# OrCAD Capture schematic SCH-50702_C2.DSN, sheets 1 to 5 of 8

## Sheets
1 01. TITLE PAGE: title: KW45B41Z-LOC; rev: C2; company: NXP Semiconductors; note: SCH-50702 PDF: SPF-50702; note: 6501 William Cannon Drive West; note: Austin, TX 78735-8598
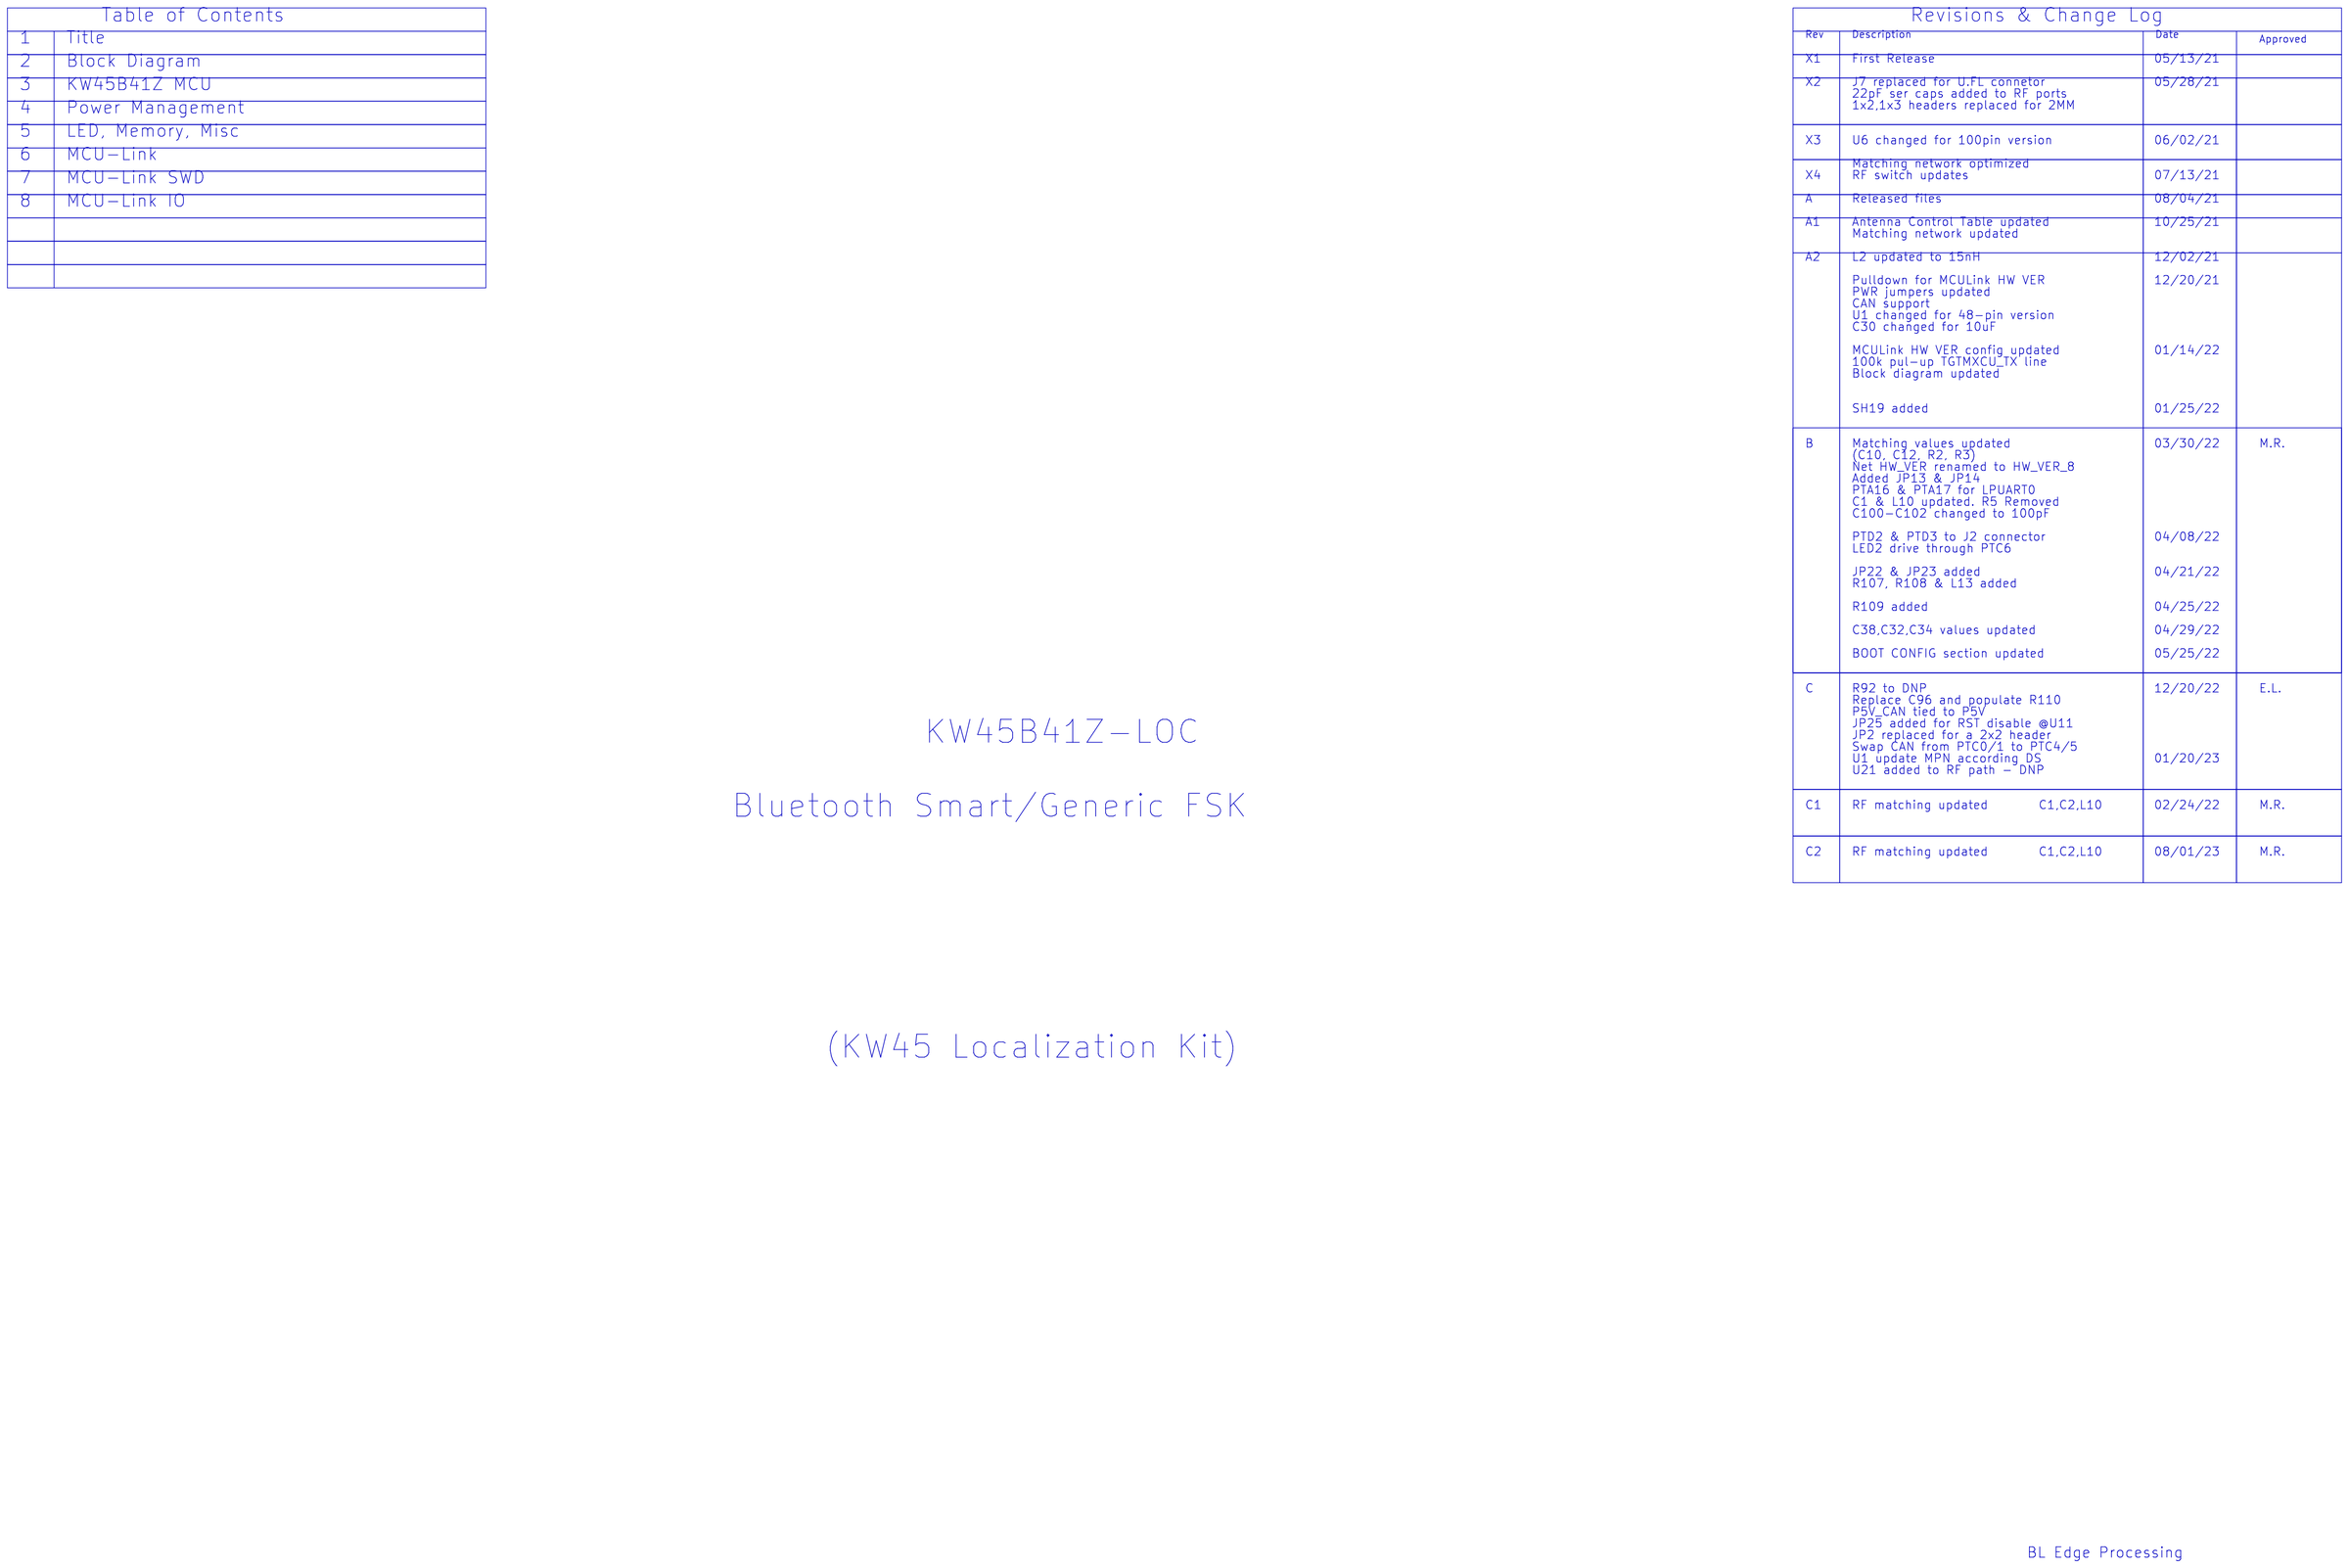
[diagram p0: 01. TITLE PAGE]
2 02. BLOCK DIAGRAM: size C
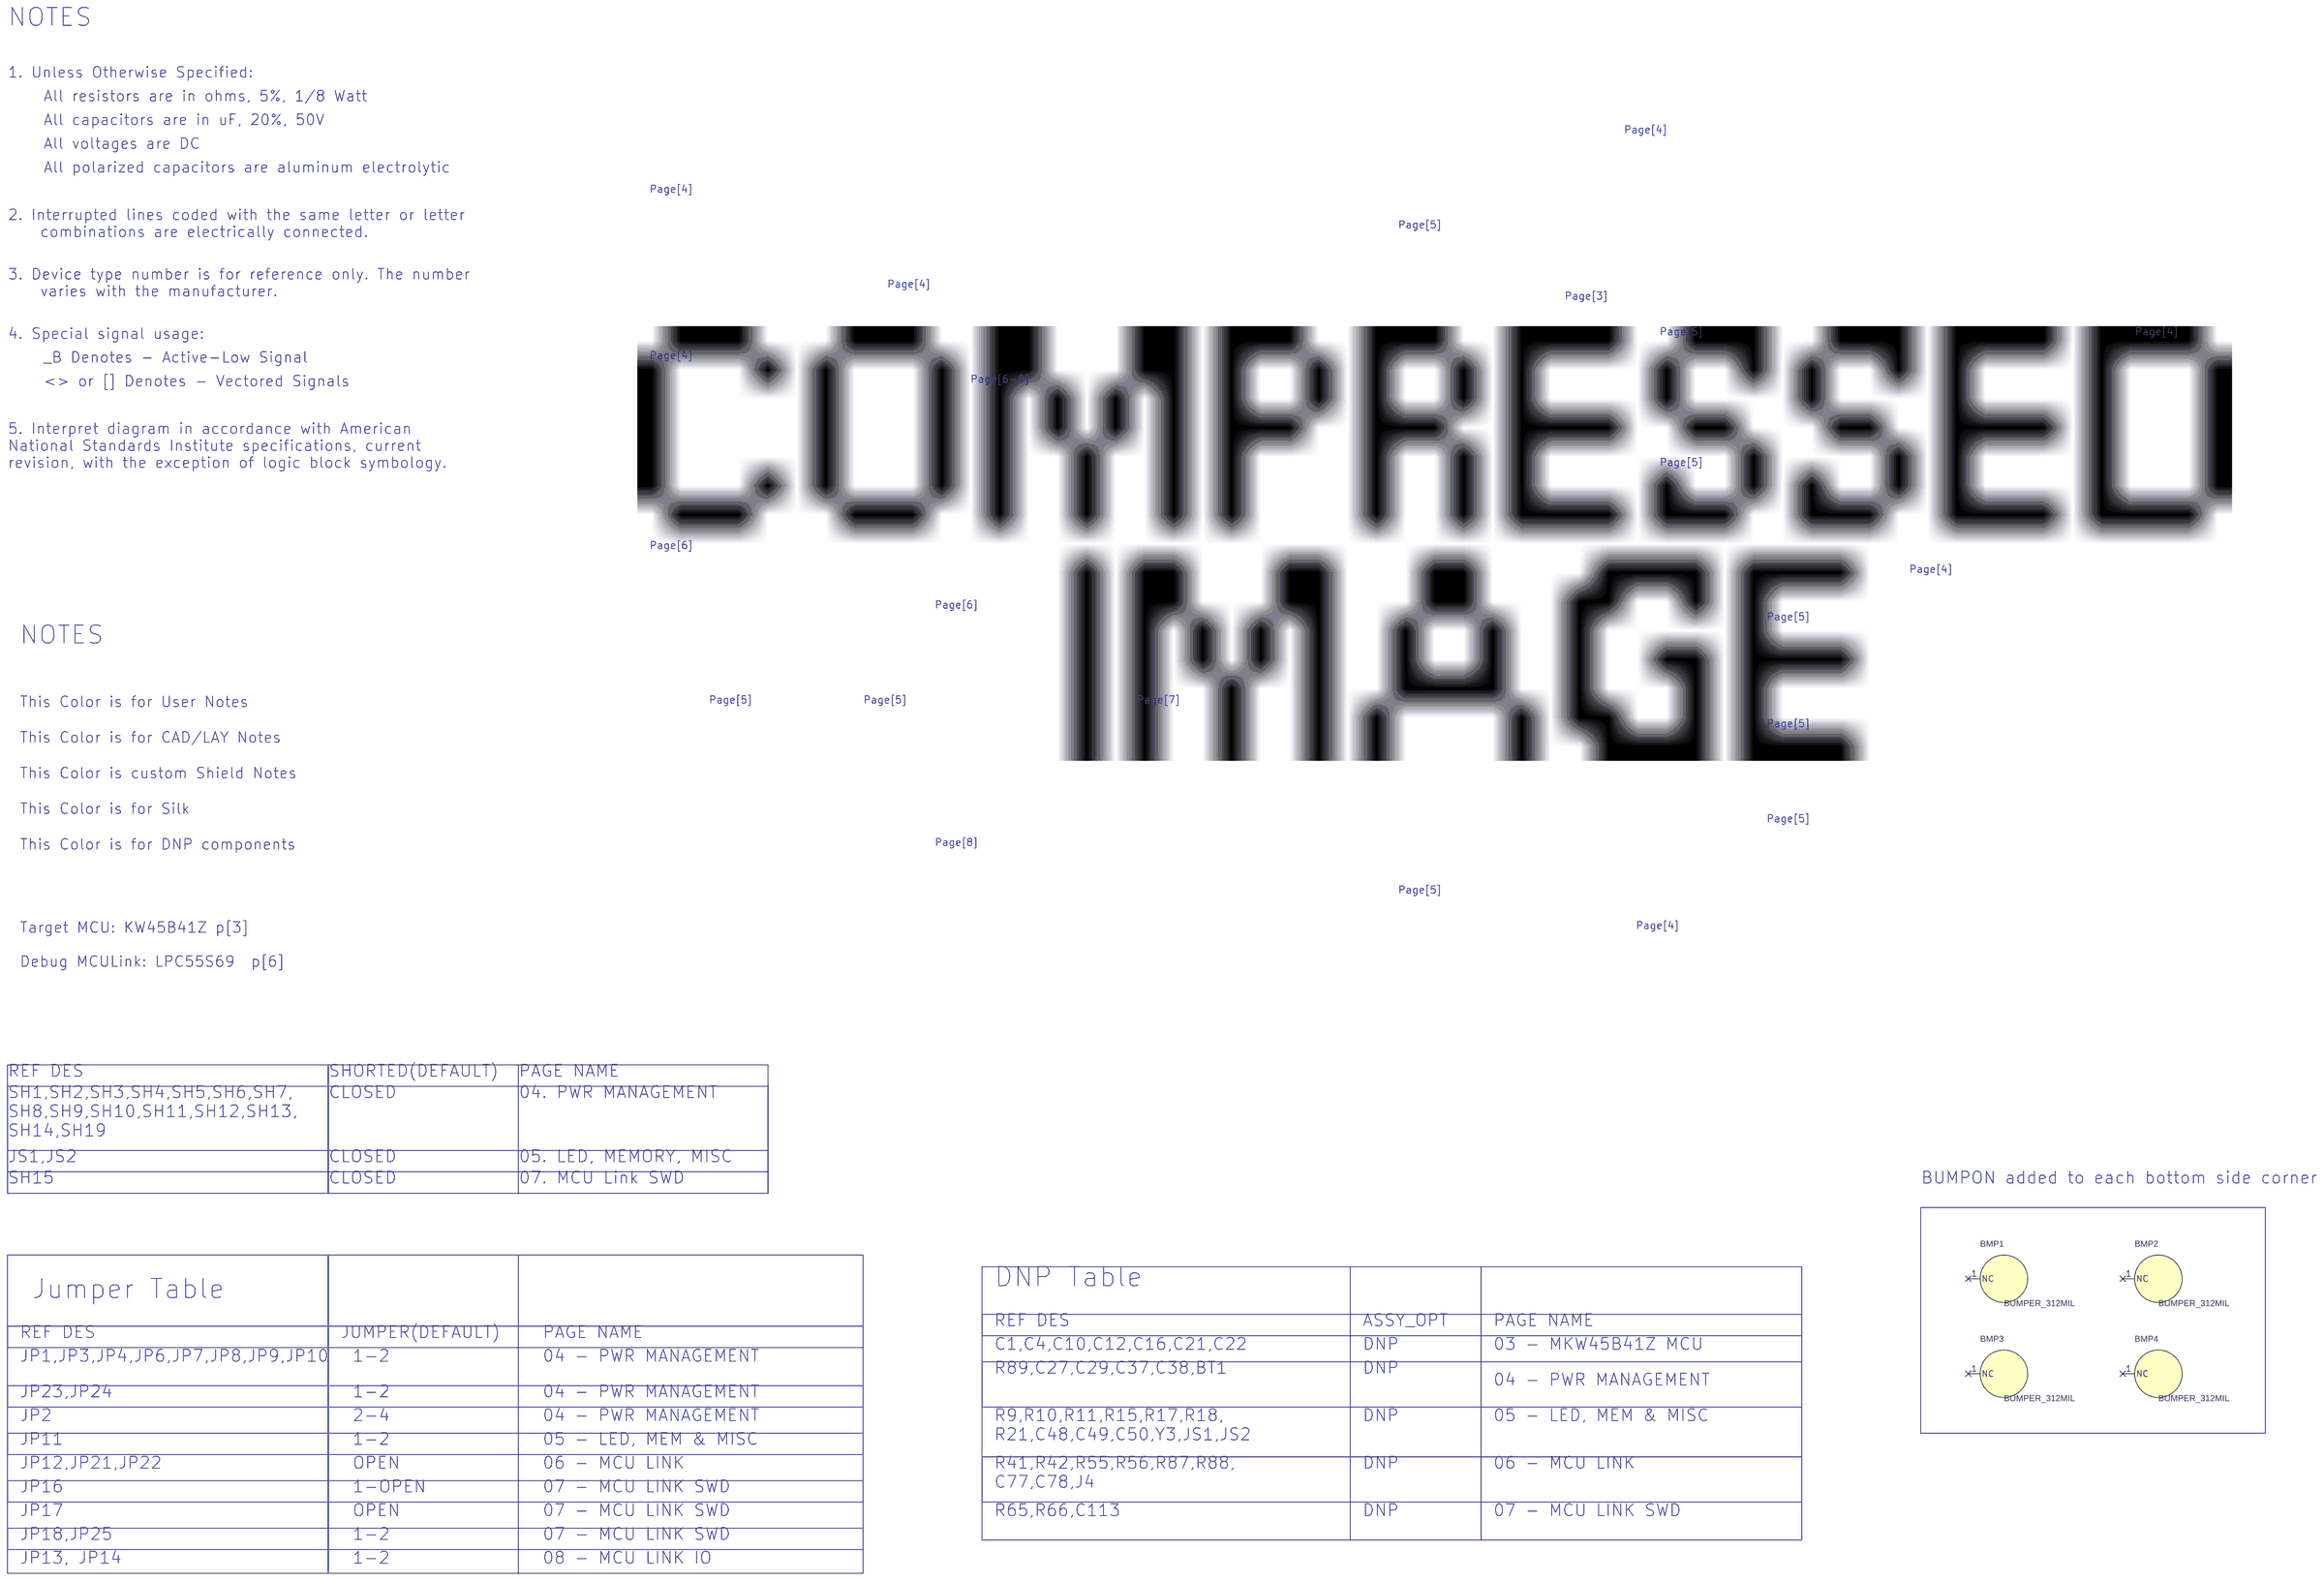
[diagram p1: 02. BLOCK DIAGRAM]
3 03. KW45B41Z MCU: size C
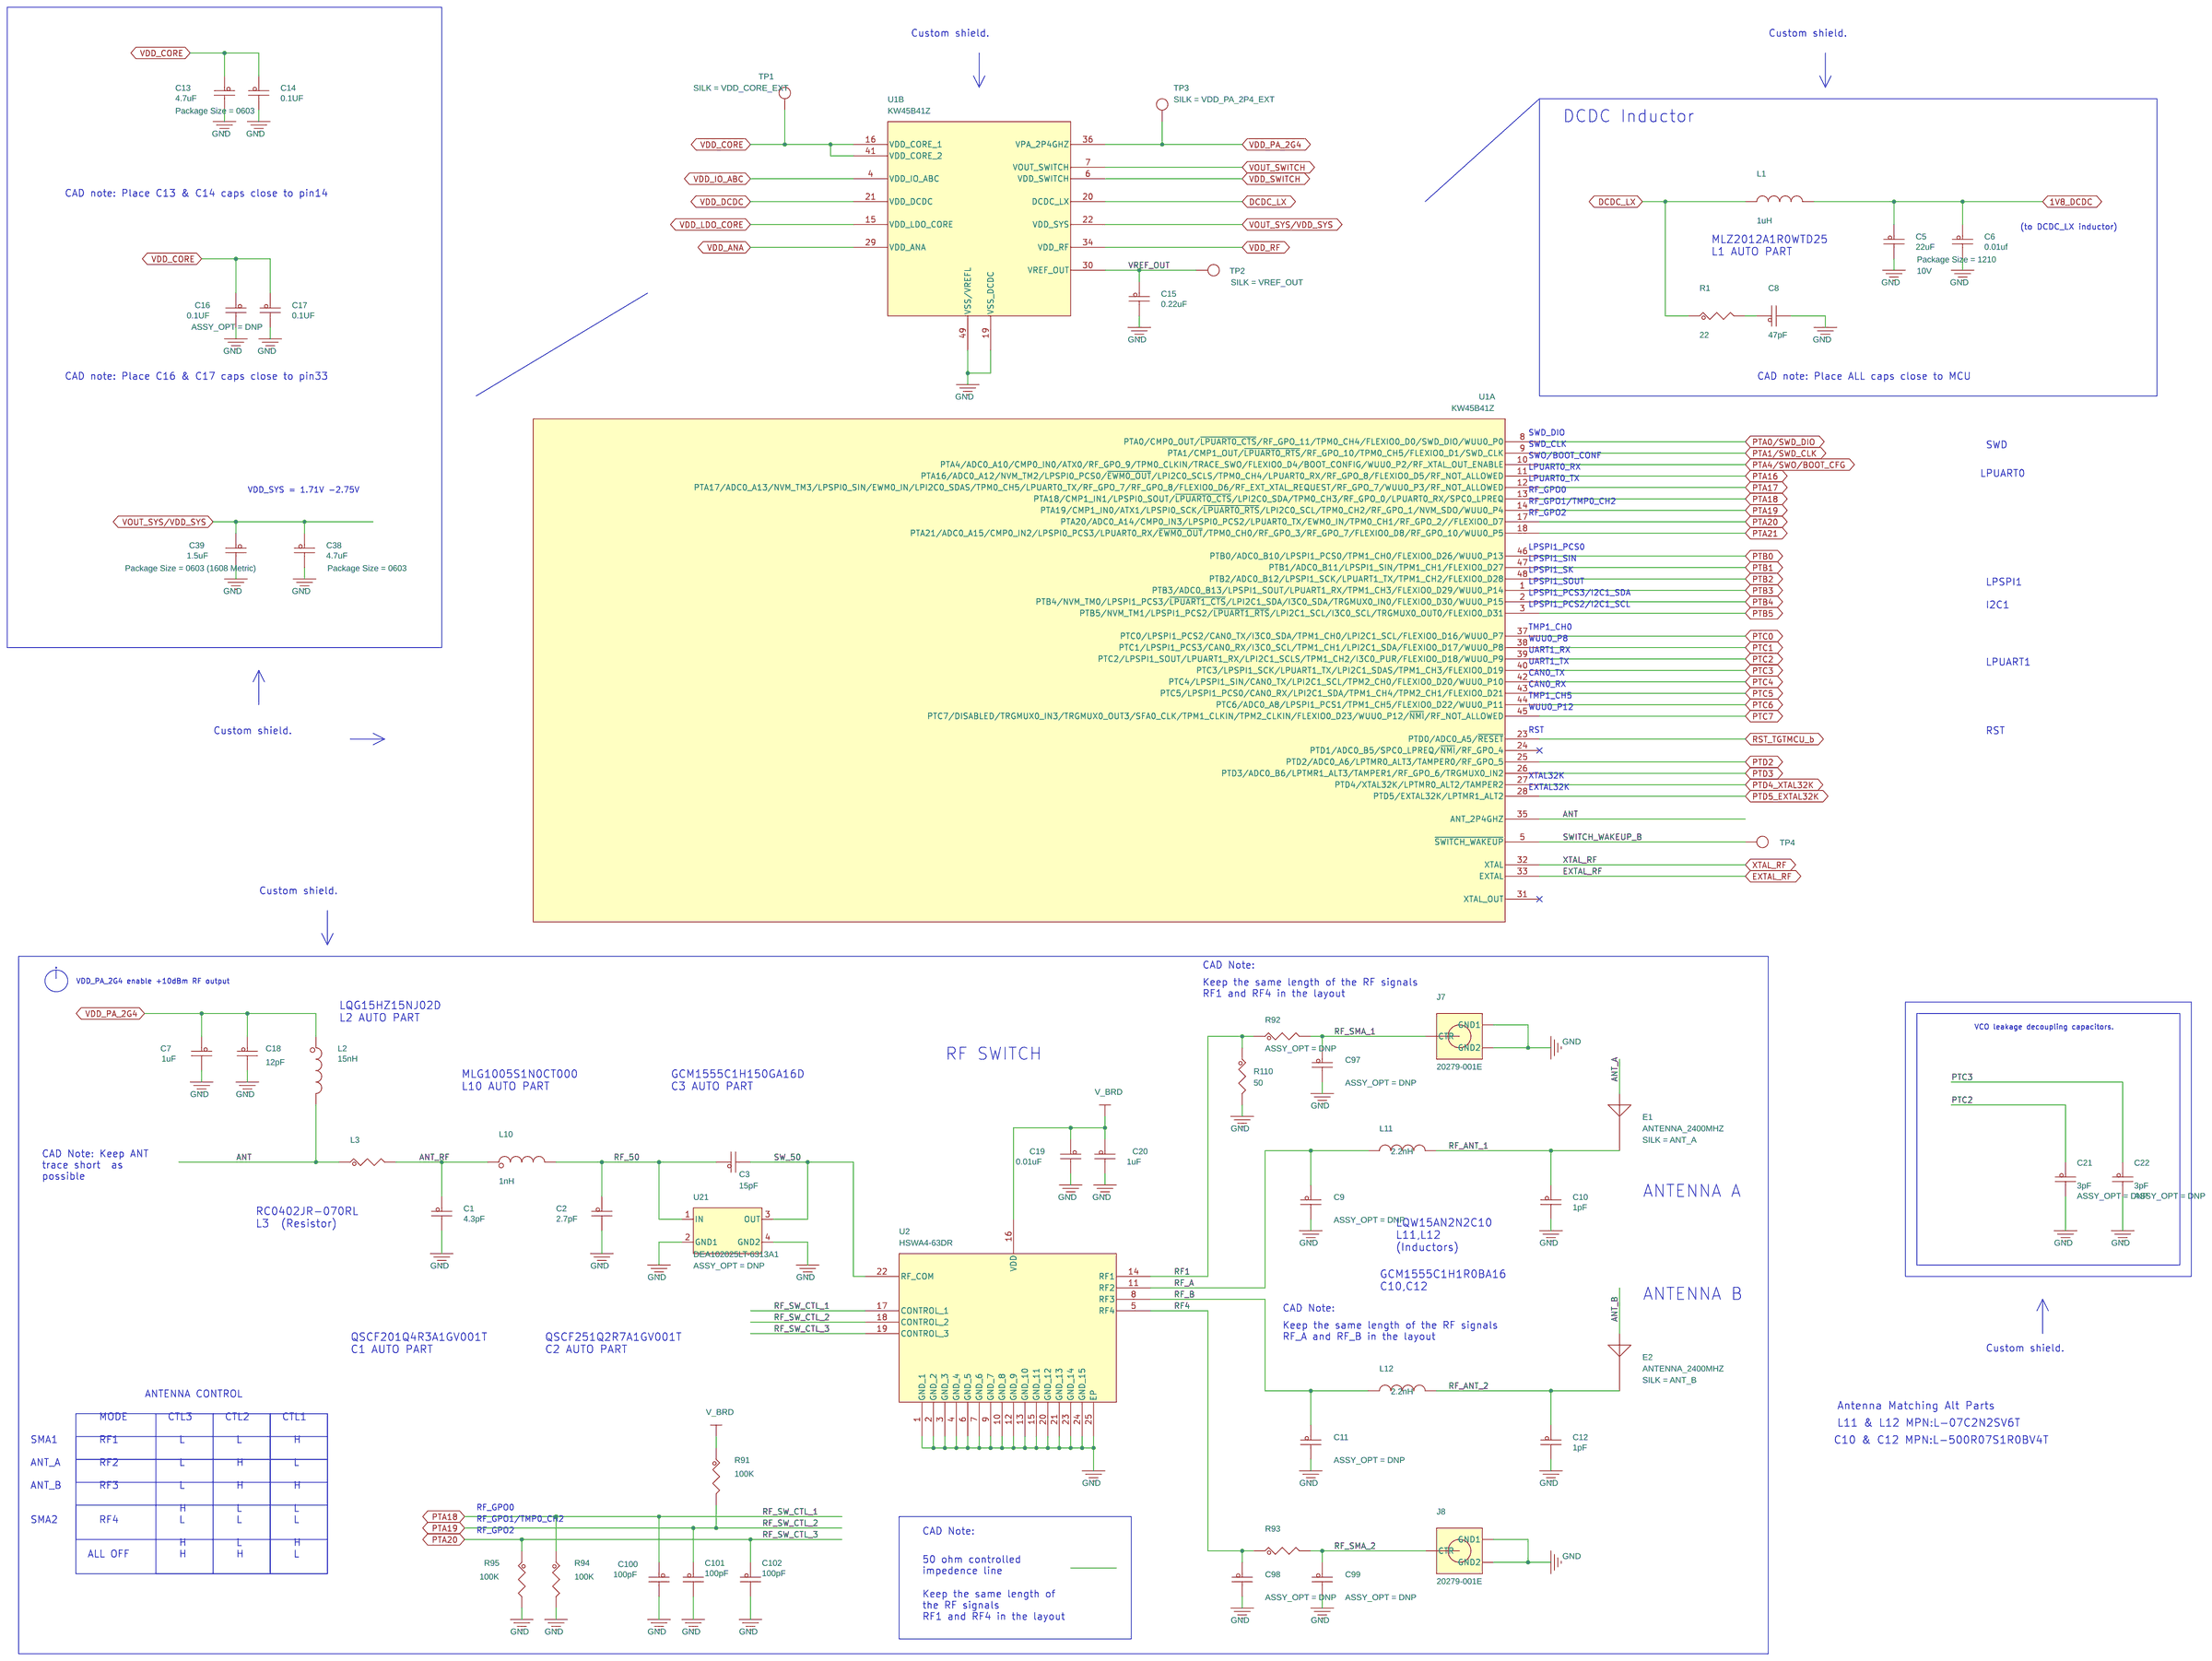
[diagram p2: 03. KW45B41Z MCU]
4 04. PWR MANAGEMENT: size C
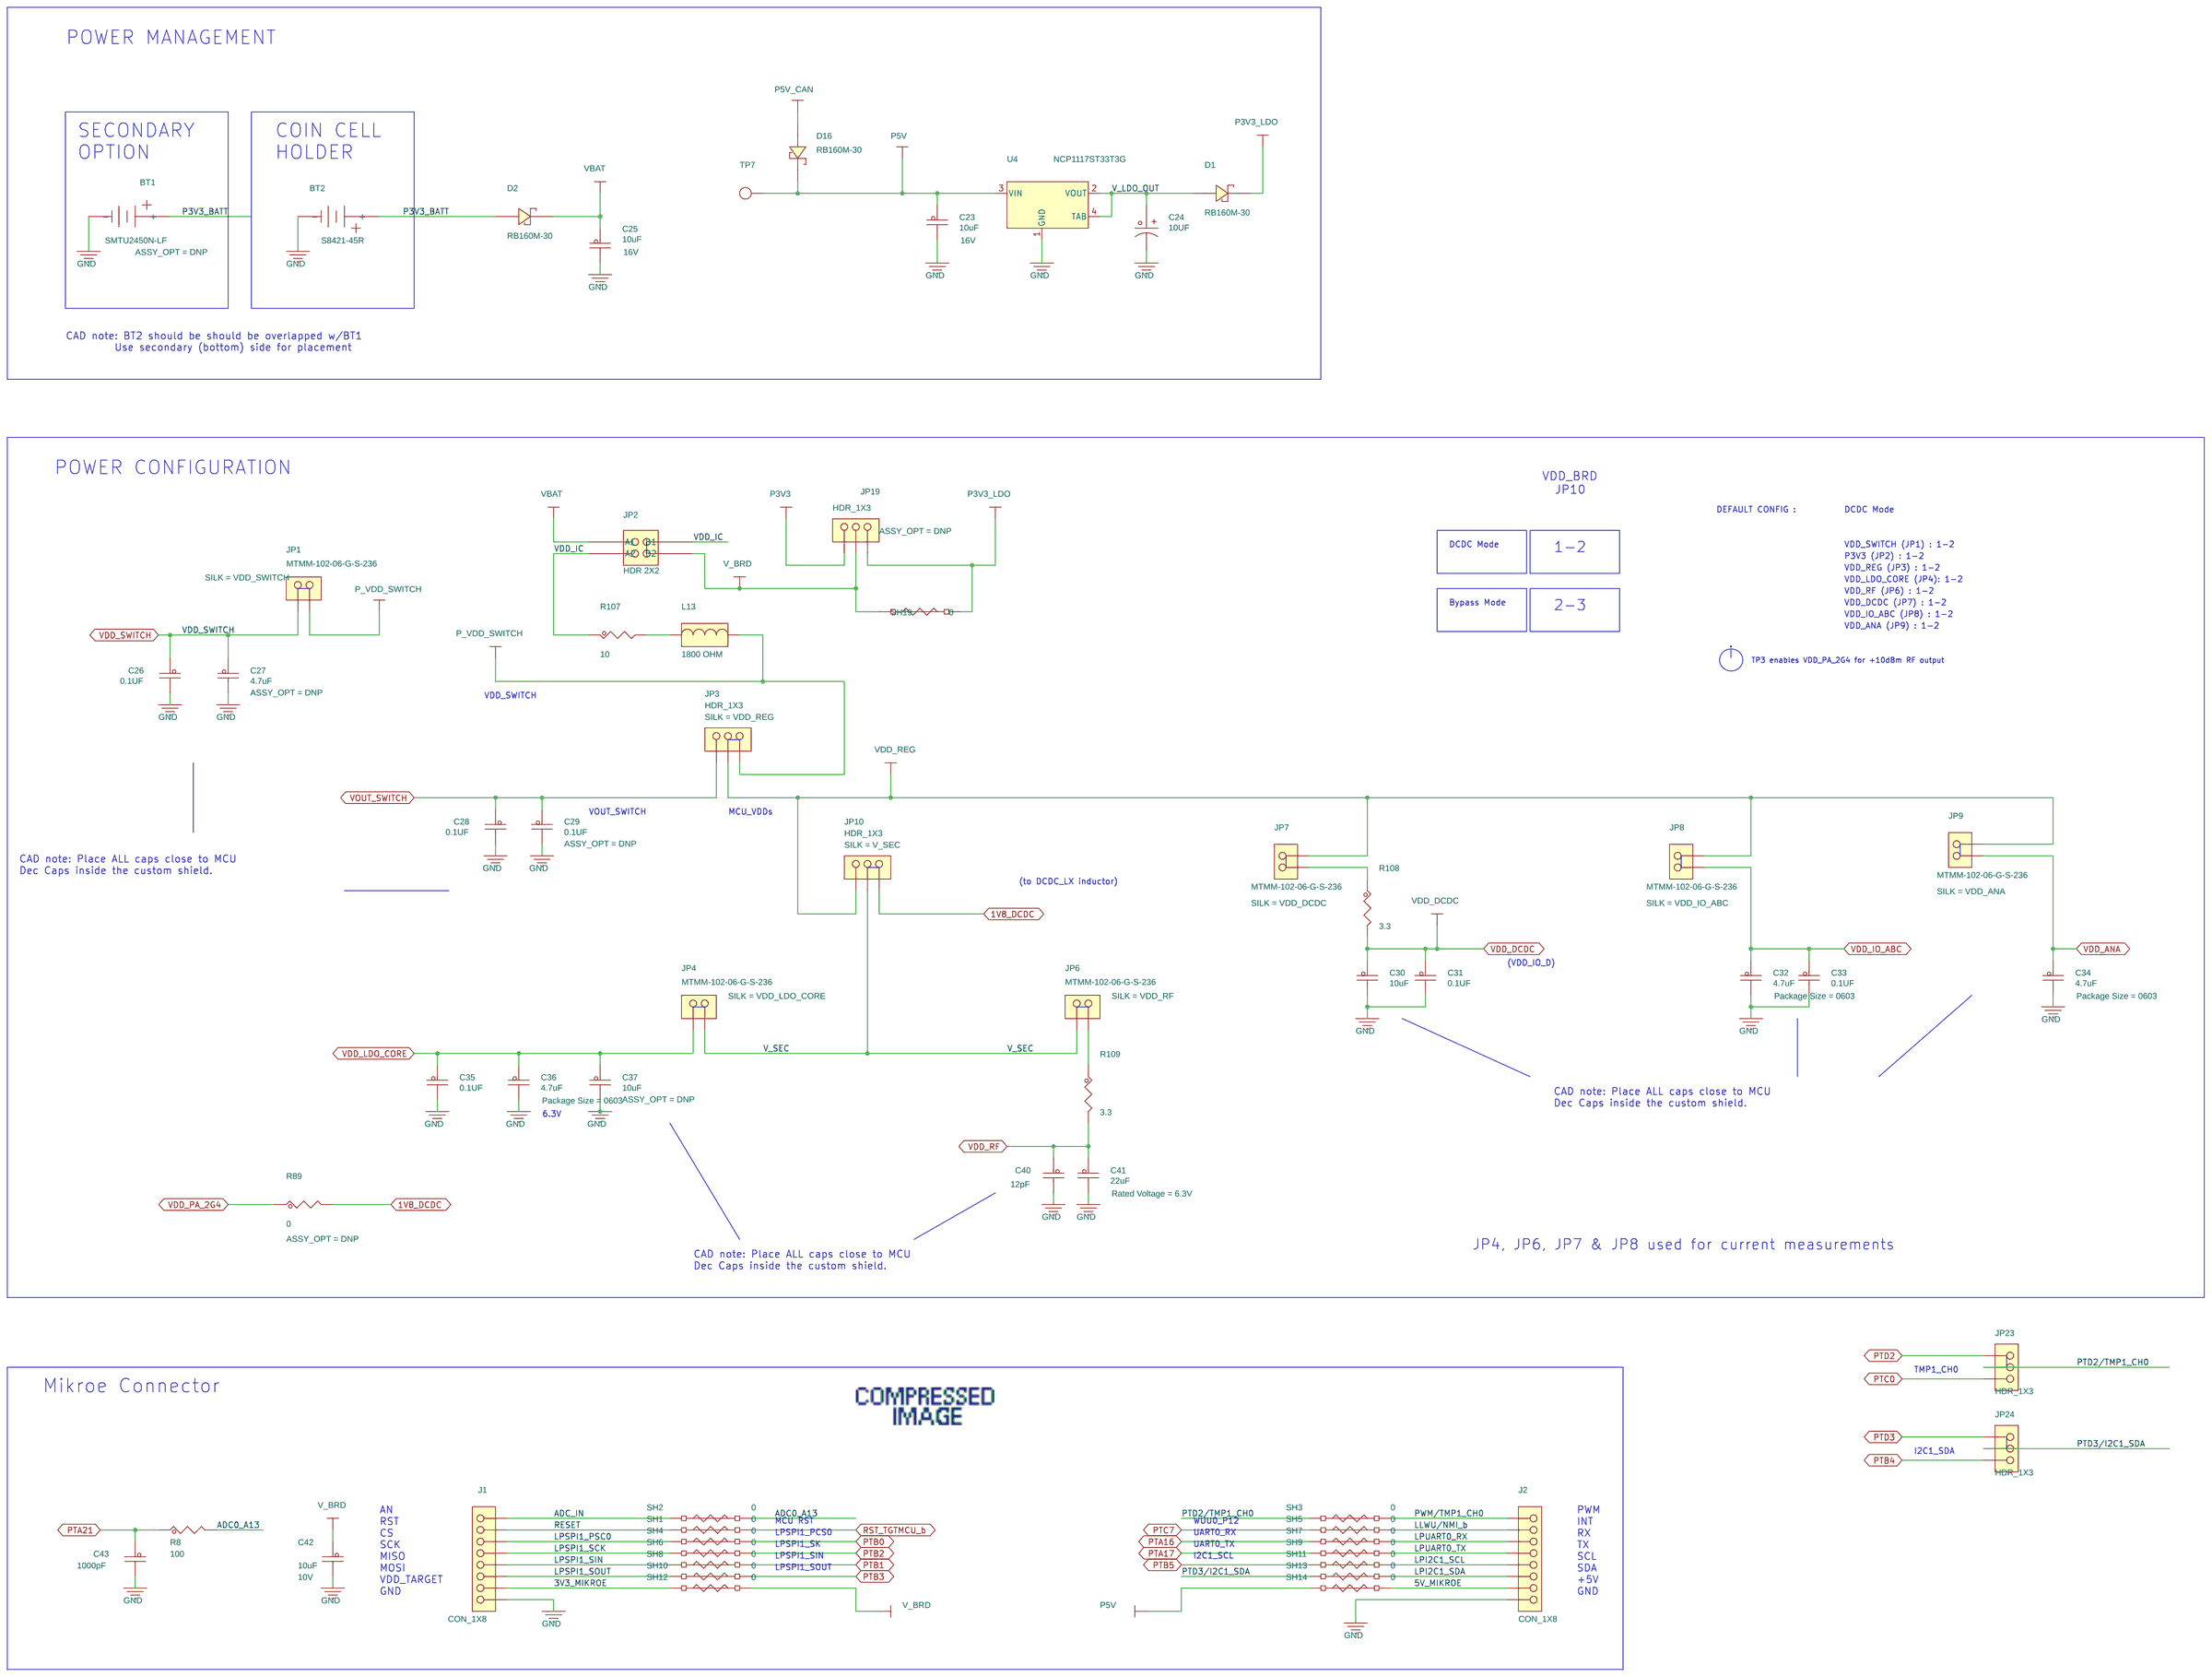
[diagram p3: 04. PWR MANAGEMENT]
5 05. LED, MEMORY, MISC: size C
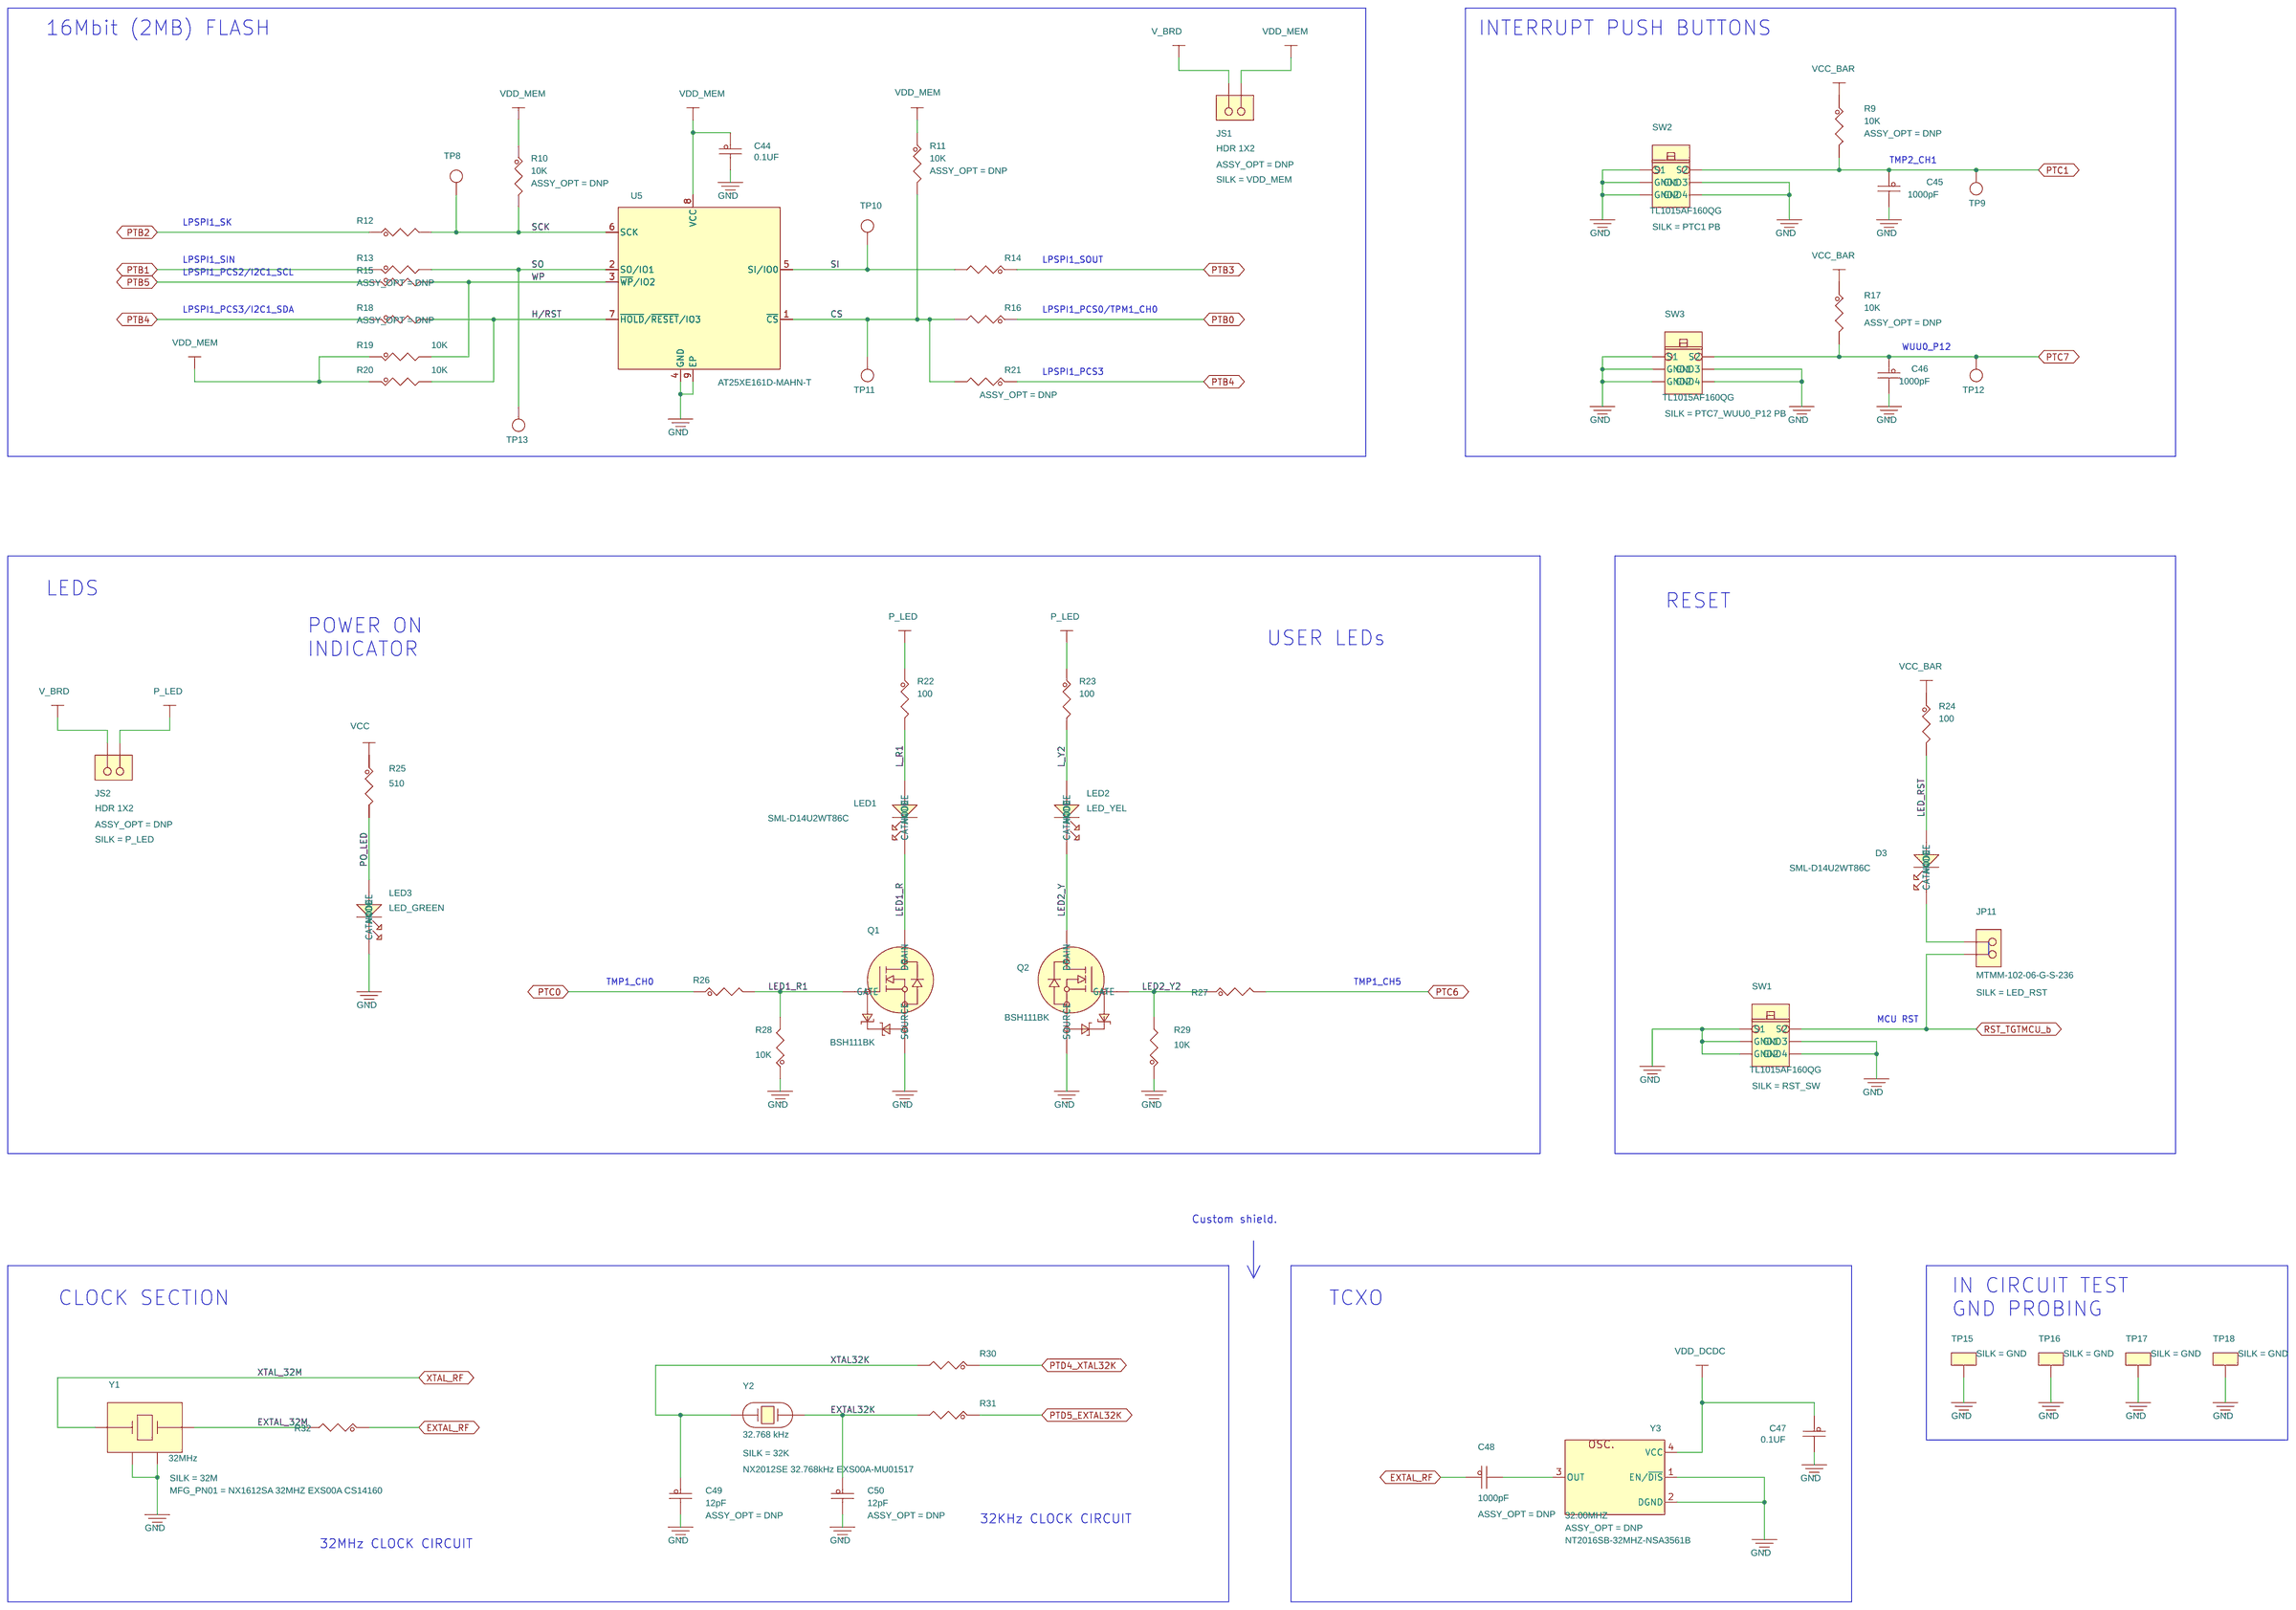
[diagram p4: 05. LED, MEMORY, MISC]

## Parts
sheet 02. BLOCK DIAGRAM
BMP1  BUMPER_312MIL  [bumper_rd_312mil]
BMP2  BUMPER_312MIL  [bumper_rd_312mil]
BMP3  BUMPER_312MIL  [bumper_rd_312mil]
BMP4  BUMPER_312MIL  [bumper_rd_312mil]
sheet 03. KW45B41Z MCU
C1  4.3pF  [CC0402_25]
C2  2.7pF  [CC0402_25]
C3  15pF  [cc0402_alt_nsp]
C5  22uF  [CC1210]
C6  0.01uf  [CC0603_OV]
C7  1uF  [cc0402_tol0p2]
C8  47pF  [CC0402_25]
C9  10PF  [CC0402_25]
C10  1pF  [CC0402_25]
C11  10PF  [CC0402_25]
C12  1pF  [CC0402_25]
C13  4.7uF  [CC0603_OV]
C14  0.1UF  [CC0402_25]
C15  0.22uF  [CC0402_25]
C16  0.1UF  [CC0402_25]
C17  0.1UF  [CC0402_25]
C18  12pF  [CC0402_25]
C19  0.01uF  [CC0201]
C20  1uF  [cc0402_tol0p2]
C21  3pF  [CC0402_25]
C22  3pF  [CC0402_25]
C38  4.7uF  [CC0603_OV]
C39  1.5uF  [CC0603_OV]
C97  10PF  [CC0402_25]
C98  10PF  [CC0402_25]
C99  10PF  [CC0402_25]
C100  100pF  [CC0402_25]
C101  100pF  [CC0402_25]
C102  100pF  [CC0402_25]
E1  ANTENNA_2400MHZ  [antenna-2450]
E2  ANTENNA_2400MHZ  [antenna-2450]
J7  20279-001E  [coax_3p_sm_20279]
J8  20279-001E  [coax_3p_sm_20279]
L1  1uH  [IND_0805]
L2  15nH  [IND_0402_POL]
L3  0  [RC0402_25]
L10  1nH  [ind_0402_pol]
L11  2.2nH  [IND_0402_L]
L12  2.2nH  [IND_0402_L]
R1  22  [RC0201]
R91  100K  [RC0402_25]
R92  0  [RC0402_25]
R93  0  [RC0402_25]
R94  100K  [RC0402_25]
R95  100K  [RC0402_25]
R110  50  [rc0402_25]
TP1  TESTLOOP_LP  [test_loop]
TP2  TESTLOOP_LP  [test_loop]
TP3  TESTLOOP_LP  [test_loop]
TP4  TESTLOOP_LP  [test_loop]
U1  KW45B41Z  [qfn_48_0p5_7x7_5p7ep]  (sections A,B)
U2  HSWA4-63DR  [qfn24_0p5_sq4_ep2p75]
U21  DEA102025LT-6313A1  [filter_1p05x0p55_sm_b]
sheet 04. PWR MANAGEMENT
BT1  SMTU2450N-LF  [CON2_BH_CR2430]
BT2  S8421-45R  [battery_holder_2032_sm]
C23  10uF  [CC0603_OV]
C24  10UF  [CC3216]
C25  10uF  [CC0603_OV]
C26  0.1UF  [CC0402_25]
C27  4.7uF  [CC0603_OV]
C28  0.1UF  [CC0402_25]
C29  0.1UF  [CC0402_25]
C30  10uF  [CC0603_OV]
C31  0.1UF  [CC0402_25]
C32  4.7uF  [CC0603_OV]
C33  0.1UF  [CC0402_25]
C34  4.7uF  [CC0603_OV]
C35  0.1UF  [CC0402_25]
C36  4.7uF  [CC0603_OV]
C37  10uF  [CC0603_OV]
C40  12pF  [CC0402_25]
C41  22uF  [CC0805_OV]
C42  10uF  [cc0402_tol0p2]
C43  1000pF  [CC0402_25]
D1  RB160M-30  [pmdu_sod123]
D2  RB160M-30  [pmdu_sod123]
D16  RB160M-30  [pmdu_sod123]
J1  CON_1X8  [con_1x8_skt_2p54_th]
J2  CON_1X8  [con_1x8_skt_2p54_th]
JP1  MTMM-102-06-G-S-236  [hdr102_tmm]
JP2  HDR 2X2  [hdr202_tmm]
JP3  HDR_1X3  [hdr103_78mil]
JP4  MTMM-102-06-G-S-236  [hdr102_tmm]
JP6  MTMM-102-06-G-S-236  [hdr102_tmm]
JP7  MTMM-102-06-G-S-236  [hdr102_tmm]
JP8  MTMM-102-06-G-S-236  [hdr102_tmm]
JP9  MTMM-102-06-G-S-236  [hdr102_tmm]
JP10  HDR_1X3  [hdr103_78mil]
JP19  HDR_1X3  [hdr103_78mil]
JP23  HDR_1X3  [hdr103_78mil]
JP24  HDR_1X3  [hdr103_78mil]
L13  1800 OHM  [IND_0402]
R8  100  [RC0402_25]
R89  0  [RC0603_OV]
R107  10  [RC0402_25]
R108  3.3  [RC0402_25]
R109  3.3  [RC0402_25]
SH1  0  [SH0402]
SH2  0  [SH0402]
SH3  0  [SH0402]
SH4  0  [SH0402]
SH5  0  [SH0402]
SH6  0  [SH0402]
SH7  0  [SH0402]
SH8  0  [SH0402]
SH9  0  [SH0402]
SH10  0  [SH0402]
SH11  0  [SH0402]
SH12  0  [SH0402]
SH13  0  [SH0402]
SH14  0  [SH0402]
SH19  0  [SH0603]
TP7  TPAD_040  [TPAD_040]
U4  NCP1117ST33T3G  [sot223]
sheet 05. LED, MEMORY, MISC
C44  0.1UF  [CC0402_25]
C45  1000pF  [CC0402_25]
C46  1000pF  [CC0402_25]
C47  0.1UF  [CC0402_25]
C48  1000pF  [CC0402_25]
C49  12pF  [CC0402_25]
C50  12pF  [CC0402_25]
D3  SML-D14U2WT86C  [led_0603]
JP11  MTMM-102-06-G-S-236  [hdr102_tmm]
JS1  HDR 1X2  [sh_hdr102_2mm_bottom]
JS2  HDR 1X2  [sh_hdr102_2mm_bottom]
LED1  SML-D14U2WT86C  [led_0603]
LED2  LED_YEL  [LED_0603]
LED3  LED_GREEN  [LED_0603]
Q1  BSH111BK  [SOT23_A]
Q2  BSH111BK  [SOT23_A]
R9  10K  [RC0402_25]
R10  10K  [RC0402_25]
R11  10K  [RC0402_25]
R12  0  [RC0402_25]
R13  0  [RC0402_25]
R14  0  [RC0402_25]
R15  0  [RC0402_25]
R16  0  [RC0402_25]
R17  10K  [RC0402_25]
R18  0  [RC0402_25]
R19  10K  [RC0402_25]
R20  10K  [RC0402_25]
R21  0  [RC0402_25]
R22  100  [RC0402_25]
R23  100  [RC0402_25]
R24  100  [RC0402_25]
R25  510  [RC0402_25]
R26  0  [RC0402_25]
R27  0  [RC0402_25]
R28  10K  [RC0402_25]
R29  10K  [RC0402_25]
R30  0  [RC0402_25]
R31  0  [RC0402_25]
R32  0  [RC0402_25]
SW1  TL1015AF160QG  [sw2_spst_4x3_sm]
SW2  TL1015AF160QG  [sw2_spst_4x3_sm]
SW3  TL1015AF160QG  [sw2_spst_4x3_sm]
TP8  TPAD_030  [TPAD_030]
TP9  TPAD_030  [TPAD_030]
TP10  TPAD_030  [TPAD_030]
TP11  TPAD_030  [TPAD_030]
TP12  TPAD_030  [TPAD_030]
TP13  TPAD_030  [TPAD_030]
TP15  TP_2P7X4P7  [tp_2p7x4p7mm]
TP16  TP_2P7X4P7  [tp_2p7x4p7mm]
TP17  TP_2P7X4P7  [tp_2p7x4p7mm]
TP18  TP_2P7X4P7  [tp_2p7x4p7mm]
U5  AT25XE161D-MAHN-T  [udfn8_0p5_3x2mm]
Y1  32MHz  [xtal4_1p6x1p2]
Y2  32.768 kHz  [xtal2_2x1p2_sm]
Y3  32.00MHZ  [osc4_2p1x1p7mm_sm]

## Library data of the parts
BMP1-BMP4 = Bumper: BUMPON CYLINDRICAL .312X.215 BLK; 3D_Mechanical_Footprint_File: http://fcl.am.freescale.net/ALLEGRO/step/bumper_rd_312mil.STEP; AGILE_PN: 280-76577; CAD_APPROVED: Yes; HEIGHT: 5.72MM; MFG_NAME01: 3M; MFG_PN01: SJ61A6; ROHS: Yes
C1 = CAP_NP: CAP CER 4.3pF 200V 1.2% C0G 0402; 3D_Mechanical_Footprint_File: http://fcl.am.freescale.net/ALLEGRO/step/cc0402_25.STEP; AGILE_PN: 150-81982; CAD_APPROVED: Yes; HEIGHT: 0.61MM; MFG_NAME01: Johanson Technology Inc.; MFG_PN01: QSCF201Q4R3A1GV001T; Package Size: 0402 (1005 Metric); Package Type: Surface Mount, MLCC; ROHS: Yes; Rated Voltage: 200V; Temp Range: -55C to +125C; Tolerance: 0.05pF (1.2%)
C2 = CAP_NP: CAP CER 2.7pF 250V 1.9% C0G 0402; 3D_Mechanical_Footprint_File: http://fcl.am.freescale.net/ALLEGRO/step/cc0402_25.STEP; AGILE_PN: 150-81981; CAD_APPROVED: Yes; HEIGHT: 0.61MM; MFG_NAME01: JOHANSON TECHNOLOGY; MFG_PN01: QSCF251Q2R7A1GV001T; Package Size: 0402 (1005 Metric); Package Type: Surface Mount, MLCC; ROHS: Yes; Rated Voltage: 250V; Temp Range: -55C to +150C; Tolerance: 1.9%
C3 = CAP_NP: CAP CER 15pF 50V 2% C0G AEC-Q200 0402; AGILE_PN: 150-80746; CAD_APPROVED: Yes; HEIGHT: 0.55MM; MFG_NAME01: MURATA; MFG_PN01: GCM1555C1H150GA16D; Package Size: 0402; Package Type: SMD; ROHS: Yes; Rated Voltage: 50V; Temp Range: -55C to +125C; Tolerance: 2%; VOLTAGE: 50V
C5 = CAP_NP: CAP CER 22uF 10V 10% X7R AEC-Q200 1210; AGILE_PN: 150-80743; CAD_APPROVED: Yes; HEIGHT: 2.7MM; MFG_NAME01: MURATA; MFG_PN01: GCM32ER71A226KE12L; Package Size: 1210; Package Type: SMD; ROHS: Yes; Rated Voltage: 10V; Temp Range: -55C to +125C; Tolerance: 10%; VOLTAGE: 10V
C6 = CAP_NP: CAP CER 0.01uF 50V 10% X7R AEC-Q200 0603; AGILE_PN: 150-79361; CAD_APPROVED: Yes; FPLIST: CC0603_OV,CC0603,0603_CC; HEIGHT: 0.9MM; MFG_NAME01: TDK; MFG_PN01: CGA3E2X7R1H103K080AA; Package Size: 0603; Package Type: 7; ROHS: Yes; Rated Voltage: 50V; Temp Range: -55C to +125C; Tolerance: 10%; VOLTAGE: 50V
C7 C20 = CAP_NP: CAP CER 1uF 10V 10% X7S AEC-Q200 0402; AGILE_PN: 150-79497; CAD_APPROVED: Yes; FPLIST: cc0402_tol0p2,cc0402_tol0p2_ov,cc0402_25_tol0p2,0402_cc_nsp; HEIGHT: 0.7MM; MFG_NAME01: MURATA; MFG_PN01: GCM155C71A105KE38D; Package Size: 0402; ROHS: Yes; Rated Voltage: 10V; Temp Range: -55C to +125C; Tolerance: 10%; VOLTAGE: 10V
C8 = CAP_NP: CAP CER 47pF 50V 5% C0G AEC-Q200 0402; AGILE_PN: 150-79041; CAD_APPROVED: Yes; HEIGHT: 0.55MM; MFG_NAME01: MURATA; MFG_PN01: GCM1555C1H470JA16; Package Size: 0402; ROHS: Yes; Rated Voltage: 50V; Temp Range: -55C to +125C; Tolerance: 5%; VOLTAGE: 50V
C9 C11 C97-C99 = CAP_NP: CAP CER 10PF 50V 5% C0G 0402; AGILE_PN: 150-75265; ASSY_OPT: DNP; CAD_APPROVED: YES; FPLIST: CC0402_25,CC0402_HD,0402_CC; HEIGHT: 0.635MM; MFG_NAME01: AVX; MFG_PN01: 04025A100JAT2A; Package Size: 0402; Package Type: 7; ROHS: Yes; Rated Voltage: 50V; TOL: 5%; Temp Range: -55C to +125C; Tolerance: 5%; VOLTAGE: 50V
C10 C12 = CAP_NP: CAP CER 1.0pF 50V 10% C0G AEC-Q200 0402; 3D_Mechanical_Footprint_File: http://fcl.am.freescale.net/ALLEGRO/step/cc0402_25.STEP; AGILE_PN: 150-81566; CAD_APPROVED: Yes; HEIGHT: 0.55MM; MFG_NAME01: MURATA; MFG_PN01: GCM1555C1H1R0BA16D; Package Size: 0402 (1005 Metric); Package Type: Surface Mount; ROHS: Yes; Rated Voltage: 50V; Temp Range: -55C to +125C; Tolerance: 0.1pF
C13 C32 C34 C36 C38 = CAP_NP: CAP CER 4.7uF 6.3V 10% X7S AEC-Q200 0603; AGILE_PN: 150-80188; CAD_APPROVED: Yes; FPLIST: CC0603_OV,CC0603,0603_CC_NSP; HEIGHT: 1MM; MFG_NAME01: MURATA; MFG_PN01: GCJ188C70J475KE02D; Package Size: 0603; ROHS: Yes; Rated Voltage: 6.3V; Temp Range: -55C to +125C; Tolerance: 10%
C14 C17 C26 C28 C31 C33 C35 C44 C47 = CAP_NP: CAP CER 0.1UF 16V 10% X7R 0402; 3D_Mechanical_Footprint_File: http://fcl.am.freescale.net/ALLEGRO/step/cc0402_25.STEP; AGILE_PN: 150-75182; CAD_APPROVED: Yes; FPLIST: CC0402_25,CC0402_HD,0402_CC,CAPC0402_L; HEIGHT: 0.635MM; MFG_NAME01: Samsung Electro-Mechanics; MFG_PN01: CL05B104KO5NNNC; ROHS: Yes; Rated Voltage: 16V; Temp Range: -55C to +125C; Tolerance: 10%; VOLTAGE: 16V
C15 = CAP_NP: CAP CER 0.22uF 16V 10% X7R AEC-Q200 0402; AGILE_PN: 150-79207; CAD_APPROVED: Yes; FPLIST: CC0402_25,CC0402_HD,0402_CC,capc0402_l; HEIGHT: 0.55MM; MFG_NAME01: MURATA; MFG_PN01: GCM155R71C224KE02; Package Type: 0402; ROHS: Yes; Rated Voltage: 16V; Temp Range: -55C to +125C; Tolerance: 10%; VOLTAGE: 16V
C16 C29 = CAP_NP: CAP CER 0.1UF 16V 10% X7R 0402; 3D_Mechanical_Footprint_File: http://fcl.am.freescale.net/ALLEGRO/step/cc0402_25.STEP; AGILE_PN: 150-75182; ASSY_OPT: DNP; CAD_APPROVED: Yes; FPLIST: CC0402_25,CC0402_HD,0402_CC,CAPC0402_L; HEIGHT: 0.635MM; MFG_NAME01: Samsung Electro-Mechanics; MFG_PN01: CL05B104KO5NNNC; ROHS: Yes; Rated Voltage: 16V; Temp Range: -55C to +125C; Tolerance: 10%; VOLTAGE: 16V
C18 C40 = CAP_NP: CAP CER 12pF 50V 5% C0G AEC-Q200 0402; AGILE_PN: 150-80457; CAD_APPROVED: Yes; FPLIST: CC0402_25,CC0402_HD,0402_CC,capc0402_l; HEIGHT: 0.55MM; MFG_NAME01: MURATA; MFG_PN01: GCM1555C1H120JA16D; Package Size: 0402; ROHS: Yes; Rated Voltage: 50V; Temp Range: -55C to +125C; Tolerance: 5%; VOLTAGE: 50V
C19 = CAP_NP: CAP CER 0.01uF 16V 10% X7R 0201; AGILE_PN: 150-80313; CAD_APPROVED: Yes; HEIGHT: 0.33MM; MFG_NAME01: MURATA; MFG_PN01: GRM033R71C103KE14D; Package Size: 0201; ROHS: Yes; Rated Voltage: 16V; Temp Range: -55C to +125C; Tolerance: 10%; VOLTAGE: 16V
C21 C22 = CAP_NP: CAP CER 3pF 50V ±0.25pF C0G AEC-Q200 0402; AGILE_PN: 150-80781; ASSY_OPT: DNP; CAD_APPROVED: YES; FPLIST: CC0402_25,CC0402_HD,0402_CC; HEIGHT: 0.55 MM; MFG_NAME01: Murata Electronics; MFG_PN01: GCQ1555C1H3R0CB01D; Package Size: 0402 (1005 Metric); Package Type: Surface Mount, MLCC; ROHS: YES; Rated Voltage: 50V; Temp Range: -55C to +125C; Tolerance: 0.25pF
C39 = CAP_NP: CAP CER 1.5uF 6.3V 10% X7R AEC-Q200 0603; 3D_Mechanical_Footprint_File: http://fcl.am.freescale.net/ALLEGRO/step/cc0603_ov.STEP; AGILE_PN: 150-81694; HEIGHT: 0.035" (0.90mm); MFG_NAME01: TDK Corporation; MFG_PN01: CGA3E1X7R0J155K080AC; Package Size: 0603 (1608 Metric); Package Type: Surface Mount, MLCC; ROHS: Yes; Rated Voltage: 6.3V; Temp Range: -55 °C to +125 °C; Tolerance: 10%
C100-C102 = CAP_NP: CAP CER 100pF 50V 5% C0G AEC-Q200 0402; AGILE_PN: 150-79021; CAD_APPROVED: Yes; HEIGHT: 0.55MM; MFG_NAME01: MURATA; MFG_PN01: GCM1555C1H101JA16B; Package Size: 0402; Package Type: Bulk Bag; ROHS: Yes; Rated Voltage: 50V; Temp Range: -55C to +125C; Tolerance: 5%; VOLTAGE: 50V
E1 = ANTENNA_2P4GHZ: ANTENNA 2.4GHZ SMT 5.0X2.0X1.1; 3D_Mechanical_Footprint_File: http://fcl.am.freescale.net/ALLEGRO/step/antenna-2450.STEP; AGILE_PN: 510-75919; CAD_APPROVED: Yes; HEIGHT: 1.3MM; MFG_NAME01: JOHANSON TECHNOLOGY; MFG_PN01: 2450AT42A100; ROHS: Yes; SILK: ANT_A
E2 = ANTENNA_2P4GHZ: ANTENNA 2.4GHZ SMT 5.0X2.0X1.1; 3D_Mechanical_Footprint_File: http://fcl.am.freescale.net/ALLEGRO/step/antenna-2450.STEP; AGILE_PN: 510-75919; CAD_APPROVED: Yes; HEIGHT: 1.3MM; MFG_NAME01: JOHANSON TECHNOLOGY; MFG_PN01: 2450AT42A100; ROHS: Yes; SILK: ANT_B
J7 J8 = UFL: CON 3 COAX RF SKT SMD 57H AU; 3D_Mechanical_Footprint_File: http://fcl.am.freescale.net/ALLEGRO/step/coax_3p_sm_20279.STEP; AGILE_PN: 211-79855; CAD_APPROVED: Yes; HEIGHT: 1.45MM; MFG_NAME01: I-PEX CO.,LTD; ROHS: Yes; Temp Range: -40°C to +90°C
L1 = INDUCTOR: IND CHK 1UH@10MHz 900MA 20%  AEC-Q200 0805; 3D_Mechanical_Footprint_File: http://fcl.am.freescale.net/ALLEGRO/step/ind_0805.STEP; AGILE_PN: 180-80855; CAD_APPROVED: Yes; HEIGHT: 1.05 MM; MFG_NAME01: TDK Corporation; MFG_PN01: MLZ2012A1R0WTD25; Package Size: 0805 (2012 Metric); ROHS: Yes; Temp Range: -55 to +125C
L2 = INDP: IND -- 15nH@100MHz 450mA 5% AEC-Q200 0402; AGILE_PN: 180-80565; CAD_APPROVED: Yes; FPLIST: IND_0402_POL,0402_CC_POL; HEIGHT: 0.55MM; MFG_NAME01: MURATA; MFG_PN01: LQG15HZ15NJ02D; Package Size: 0402 (1005 Metric); ROHS: Yes; Temp Range: -55C to +125C
L3 R12-R14 R16 R26 R27 R30-R32 R93 = RES: RES MF ZERO OHM 1/16W 5% 0402; AGILE_PN: 470-75394; CAD_APPROVED: Yes; FPLIST: RC0402_25,RC0402_HD,RC0402_X2,0402_CC; HEIGHT: 0.45 MM; MFG_NAME01: BOURNS; MFG_PN01: CR0402-J/-000GLF; ROHS: Yes; Tolerance: 5%; VOLTAGE: 1/16W
L10 = INDP: IND -- 0.001uH@100MHz 1A 20% 0402; 3D_Mechanical_Footprint_File: http://fcl.am.freescale.net/ALLEGRO/step/ind_0402_pol.STEP; AGILE_PN: 180-81737; CAD_APPROVED: Yes; HEIGHT: 0.55 MM; MFG_NAME01: TDK Corporation; MFG_PN01: MLG1005S1N0CT000; Package Size: 0402 (1005 Metric); ROHS: Yes; Temp Range: -55 °C to +125 °C
L11 L12 = INDUCTOR: IND -- 2.2nH@100MHz 1A 0.2nH 0402; 3D_Mechanical_Footprint_File: http://fcl.am.freescale.net/ALLEGRO/step/ind_0402_l.STEP; AGILE_PN: 180-81567; CAD_APPROVED: Yes; HEIGHT: 0.60MM; MFG_NAME01: Murata Electronics; MFG_PN01: LQW15AN2N2C10D; Package Size: 0402 (1005 Metric); ROHS: Yes; Temp Range: -55°C ~ 125°C
R1 = RES: RES TF 22OHM 1/20W 1% AEC-Q200 0201; AGILE_PN: 470-81170; CAD_APPROVED: Yes; HEIGHT: 0.26MM; MFG_NAME01: KOA SPEER; MFG_PN01: RK73H1HTTC22R0F; ROHS: Yes; Tolerance: 1%; VOLTAGE: 25V
R91 R94 R95 = RES: RES MF 100K 1/16W 1% 0402; AGILE_PN: 470-76240; CAD_APPROVED: Yes; FPLIST: RC0402_25,RC0402_HD,0402_CC; HEIGHT: 0.4MM; MFG_NAME01: BOURNS; MFG_PN01: CR0402-FX-1003GLF; ROHS: Yes; Tolerance: 1%
R15 R18 R21 R92 = RES: RES MF ZERO OHM 1/16W 5% 0402; AGILE_PN: 470-75394; ASSY_OPT: DNP; CAD_APPROVED: Yes; FPLIST: RC0402_25,RC0402_HD,RC0402_X2,0402_CC; HEIGHT: 0.45 MM; MFG_NAME01: BOURNS; MFG_PN01: CR0402-J/-000GLF; ROHS: Yes; Tolerance: 5%; VOLTAGE: 1/16W
R110 = RES: RES MF 50 OHM  1/16W 5% AEC-Q200 0402; 3D_Mechanical_Footprint_File: http://fcl.am.freescale.net/ALLEGRO/step/rc0402_25.STEP; AGILE_PN: 470-82979; CAD_APPROVED: Yes; HEIGHT: 0.37MM; MFG_NAME01: YAGEO AMERICA; MFG_PN01: AC0402JR-0750RL; Package Size: 0402 (1005 Metric); ROHS: Yes; Temp Range: -55°C ~ 155°C; Tolerance: 5%
TP1 = TESTLOOP: TEST POINT PC MULTIPURPOSE LOW PROFILE PAD 40MIL DIA TH; AGILE_PN: 210-79469; CAD_APPROVED: Yes; HEIGHT: 2.54MM; MFG_NAME01: COMPONENTS CORPORATION; MFG_PN01: TP-103-03-T; ROHS: Yes; SILK: VDD_CORE_EXT
TP2 = TESTLOOP: TEST POINT PC MULTIPURPOSE LOW PROFILE PAD 40MIL DIA TH; AGILE_PN: 210-79469; CAD_APPROVED: Yes; HEIGHT: 2.54MM; MFG_NAME01: COMPONENTS CORPORATION; MFG_PN01: TP-103-03-T; ROHS: Yes; SILK: VREF_OUT
TP3 = TESTLOOP: TEST POINT PC MULTIPURPOSE LOW PROFILE PAD 40MIL DIA TH; AGILE_PN: 210-79469; CAD_APPROVED: Yes; HEIGHT: 2.54MM; MFG_NAME01: COMPONENTS CORPORATION; MFG_PN01: TP-103-03-T; ROHS: Yes; SILK: VDD_PA_2P4_EXT
TP4 = TESTLOOP: TEST POINT PC MULTIPURPOSE LOW PROFILE PAD 40MIL DIA TH; AGILE_PN: 210-79469; CAD_APPROVED: Yes; HEIGHT: 2.54MM; MFG_NAME01: COMPONENTS CORPORATION; MFG_PN01: TP-103-03-T; ROHS: Yes
U1 = KW45B41Z_48EP: IC MCU 32BIT ARM CORTEX-M33 FLASH 1MB SRAM 1.71-3.6V AEC-Q100 HVQFN48; 3D_Mechanical_Footprint_File: http://fcl.am.freescale.net/ALLEGRO/step/qfn_48_0p5_7x7_5p7ep.STEP; AGILE_PN: 344-02623; CAD_APPROVED: yes; HEIGHT: 1 MM; MFG_NAME01: NXP SEMICONDUCTOR; MFG_PN01: KW45B41Z83AFTB; ROHS: Yes; Temp Range: -40 to 125 C
U2 = HSWA4-63DR: IC RF SWITCH SP4T 30-6000MHz 2.3-5.5V QFN24; 3D_Mechanical_Footprint_File: http://fcl.am.freescale.net/ALLEGRO/step/qfn24_0p5_sq4_ep2p75.step; AGILE_PN: 315-82975; CAD_APPROVED: Yes; HEIGHT: 0.8MM; MFG_NAME01: Mini-Circuits; MFG_PN01: HSWA4-63DR+; Package Size: 4 x 4 x 0.8 mm; ROHS: Yes; Supply Voltage: 2.3-5.5V; Temp Range: -40°C to +105°C
U21 = B9014_4P: IC RF FILTER LOW PASS 1880-2025MHz 0402; 3D_Mechanical_Footprint_File: http://fcl.am.freescale.net/ALLEGRO/step/filter_1p05x0p55_sm_b.STEP; AGILE_PN: 315-84062; ASSY_OPT: DNP; CAD_APPROVED: Yes; HEIGHT: 0.4MM; MFG_NAME01: TDK; Package Size: 0.039" L x 0.020" W (1.00mm x 0.50mm); ROHS: Yes; Temp Range: -40°C to 85°C
BT1 = BATTERY: BATTERY HOLDER FOR CR2450N SMT; AGILE_PN: 801-76096; ASSY_OPT: DNP; CAD_APPROVED: Yes; HEIGHT: 7.7MM; MFG_NAME01: RENATA BATTERIES; ROHS: Yes
BT2 = BATTERY: BATTERY HOLDER CR2032 SMD; 3D_Mechanical_Footprint_File: http://fcl.am.freescale.net/ALLEGRO/step/battery_holder_2032_sm.STEP; AGILE_PN: 801-76278; CAD_APPROVED: Yes; HEIGHT: 5.5 MM; MFG_NAME01: HARWIN INC; Package Type: SMT; ROHS: Yes; Temp Range: -40° C to +105° C; Temp_Range: -40° C to +105° C
C23 C25 C30 = CAP_NP: CAP CER 10uF 16V 20% X5R 0603; AGILE_PN: 150-79092; CAD_APPROVED: Yes; FPLIST: CC0603_OV,CC0603,0603_CC; HEIGHT: 1mm; MFG_NAME01: YAGEO AMERICA; MFG_PN01: CC0603MRX5R7BB106; ROHS: Yes; Rated Voltage: 16V; Temp Range: -55C to +85C; Tolerance: 20%; VOLTAGE: 16V
C24 = CAP_POL: CAP TANT ESR=0.900 OHMS 10UF 10V 20% -- 3216-18; 3D_Mechanical_Footprint_File: http://fcl.am.freescale.net/ALLEGRO/step/cc3216.step; AGILE_PN: 150-75257; CAD_APPROVED: Yes; HEIGHT: 1.8MM; MFG_NAME01: AVX; MFG_PN01: TPSA106M010R0900; Package Size: 3216-18; Package Type: 7" T/R; ROHS: Yes; Rated Voltage: 10V; Tolerance: 20%; VOLTAGE: 10V
C27 = CAP_NP: CAP CER 4.7uF 6.3V 10% X7S AEC-Q200 0603; AGILE_PN: 150-80188; ASSY_OPT: DNP; CAD_APPROVED: Yes; FPLIST: CC0603_OV,CC0603,0603_CC_NSP; HEIGHT: 1MM; MFG_NAME01: MURATA; MFG_PN01: GCJ188C70J475KE02D; Package Size: 0603; ROHS: Yes; Rated Voltage: 6.3V; Temp Range: -55C to +125C; Tolerance: 10%
C37 = CAP_NP: CAP CER 10uF 16V 20% X5R 0603; AGILE_PN: 150-79092; ASSY_OPT: DNP; CAD_APPROVED: Yes; FPLIST: CC0603_OV,CC0603,0603_CC; HEIGHT: 1mm; MFG_NAME01: YAGEO AMERICA; MFG_PN01: CC0603MRX5R7BB106; ROHS: Yes; Rated Voltage: 16V; Temp Range: -55C to +85C; Tolerance: 20%; VOLTAGE: 16V
C41 = CAP_NP: CAP CER 22uF 6.3V 20% X7T AEC-Q200 0805; 3D_Mechanical_Footprint_File: http://fcl.am.freescale.net/ALLEGRO/step/cc0805_ov.STEP; AGILE_PN: 150-81462; CAD_APPROVED: Yes; HEIGHT: 1.55MM; MFG_NAME01: TDK Corporation; MFG_PN01: CGA4J1X7T0J226M125AC; Package Type: Surface Mount, MLCC; ROHS: Yes; Rated Voltage: 6.3V; Temp Range: -55C to +125C; Tolerance: 20%
C42 = CAP_NP: CAP CER 10uF 10V 20% X5R 0402_WIDE; AGILE_PN: 150-79255; CAD_APPROVED: Yes; FPLIST: CC0402_25,CC0402_HD,0402_CC; HEIGHT: 0.7MM; MFG_NAME01: NIC COMPONENTS CORP; MFG_PN01: NMC0402X5R106M10TRPF; ROHS: Yes; Rated Voltage: 10V; Temp Range: -55C to +85C; Tolerance: 20%; VOLTAGE: 10V
C43 C45 C46 = CAP_NP: CAP CER 1000PF 50V 5% C0G 0402; AGILE_PN: 150-76334; CAD_APPROVED: Yes; FPLIST: CC0402_25,CC0402_HD,0402_CC; HEIGHT: 0.55MM; MFG_NAME01: MURATA; MFG_PN01: GRM1555C1H102JA01D; Package Size: 0402; Package Type: 180mm Paper Tape; ROHS: Yes; Rated Voltage: 50V; Temp Range: -55C to +125C; Tolerance: 5%; VOLTAGE: 50V
D1 D2 D16 = DIODE_SCHTKY: DIODE SCH 1A 30V SOD123; 3D_Mechanical_Footprint_File: http://fcl.am.freescale.net/ALLEGRO/step/pmdu_sod123.STEP; AGILE_PN: 480-79681; CAD_APPROVED: Yes; HEIGHT: 0.9MM; MFG_NAME01: ROHM; MFG_PN01: RB160M-30TR; ROHS: Yes
J1 J2 = CONN_HDR_8X1: CON 1X8 SKT TH 100MIL SP 335H AU 104L; 3D_Mechanical_Footprint_File: http://fcl.am.freescale.net/ALLEGRO/step/con_1x8_skt_2p54_th_170h.STEP; AGILE_PN: 210-79539; CAD_APPROVED: Yes; HEIGHT: 8.51MM; MFG_NAME01: SAMTEC; MFG_PN01: SSW-108-01-G-S; ROHS: Yes; Temp Range: -55°C to +125°C
JP1 = CONN_HDR_2X1: HDR 1X2 TH 2MM SP 300H AU 102L; AGILE_PN: 210-80456; CAD_APPROVED: Yes; HEIGHT: 7.62MM; Jumper (Default): 1-2; MFG_NAME01: SAMTEC; ROHS: Yes; SILK: VDD_SWITCH; Temp_Range: -55°C to +105°C
JP2 = CONN_HDR_2X2: HDR 2X2 TH 2MM CTR 217H AU 110L; 3D_Mechanical_Footprint_File: http://fcl.am.freescale.net/ALLEGRO/step/hdr202_tmm.STEP; AGILE_PN: 210-77113; CAD_APPROVED: Yes; HEIGHT: 5.33MM; MFG_NAME01: SAMTEC; MFG_PN01: TMM-102-02-G-D; ROHS: Yes
JP3 = CONN_HDR_3X1: HDR 1X3 TH 2MM SP 295H AU 102L; AGILE_PN: 210-80201; CAD_APPROVED: Yes; HEIGHT: 7.5 MM; MFG_NAME01: SAMTEC; MFG_PN01: MTMM-103-06-G-S-236; ROHS: Yes; SILK: VDD_REG; Temp_Range: -55°C to +125°C
JP4 = CONN_HDR_2X1: HDR 1X2 TH 2MM SP 300H AU 102L; AGILE_PN: 210-80456; CAD_APPROVED: Yes; HEIGHT: 7.62MM; Jumper (Default): 1-2; MFG_NAME01: SAMTEC; ROHS: Yes; SILK: VDD_LDO_CORE; Temp_Range: -55°C to +105°C
JP6 = CONN_HDR_2X1: HDR 1X2 TH 2MM SP 300H AU 102L; AGILE_PN: 210-80456; CAD_APPROVED: Yes; HEIGHT: 7.62MM; Jumper (Default): 1-2; MFG_NAME01: SAMTEC; ROHS: Yes; SILK: VDD_RF; Temp_Range: -55°C to +105°C
JP7 = CONN_HDR_2X1: HDR 1X2 TH 2MM SP 300H AU 102L; AGILE_PN: 210-80456; CAD_APPROVED: Yes; HEIGHT: 7.62MM; Jumper (Default): 1-2; MFG_NAME01: SAMTEC; ROHS: Yes; SILK: VDD_DCDC; Temp_Range: -55°C to +105°C
JP8 = CONN_HDR_2X1: HDR 1X2 TH 2MM SP 300H AU 102L; AGILE_PN: 210-80456; CAD_APPROVED: Yes; HEIGHT: 7.62MM; Jumper (Default): 1-2; MFG_NAME01: SAMTEC; ROHS: Yes; SILK: VDD_IO_ABC; Temp_Range: -55°C to +105°C
JP9 = CONN_HDR_2X1: HDR 1X2 TH 2MM SP 300H AU 102L; AGILE_PN: 210-80456; CAD_APPROVED: Yes; HEIGHT: 7.62MM; Jumper (Default): 1-2; MFG_NAME01: SAMTEC; ROHS: Yes; SILK: VDD_ANA; Temp_Range: -55°C to +105°C
JP10 = CONN_HDR_3X1: HDR 1X3 TH 2MM SP 295H AU 102L; AGILE_PN: 210-80201; CAD_APPROVED: Yes; HEIGHT: 7.5 MM; MFG_NAME01: SAMTEC; MFG_PN01: MTMM-103-06-G-S-236; ROHS: Yes; SILK: V_SEC; Temp_Range: -55°C to +125°C
JP19 = CONN_HDR_3X1: HDR 1X3 TH 2MM SP 295H AU 102L; AGILE_PN: 210-80201; ASSY_OPT: DNP; CAD_APPROVED: Yes; HEIGHT: 7.5 MM; MFG_NAME01: SAMTEC; MFG_PN01: MTMM-103-06-G-S-236; ROHS: Yes; Temp_Range: -55°C to +125°C
JP23 JP24 = CONN_HDR_3X1: HDR 1X3 TH 2MM SP 295H AU 102L; AGILE_PN: 210-80201; CAD_APPROVED: Yes; HEIGHT: 7.5 MM; MFG_NAME01: SAMTEC; MFG_PN01: MTMM-103-06-G-S-236; ROHS: Yes; Temp_Range: -55°C to +125°C
L13 = BEAD: IND FER BEAD 1800 OHM@100MHZ 0.2A 25% 0402; AGILE_PN: 180-78363; CAD_APPROVED: Yes; HEIGHT: 0.55MM; MFG_NAME01: MURATA; MFG_PN01: BLM15HD182SN1; ROHS: Yes
R8 R22-R24 = RES: RES MF 100 OHM 1/16W 5% 0402; AGILE_PN: 470-75591; CAD_APPROVED: Yes; FPLIST: RC0402_25,RC0402_HD,RC0402_X2,0402_CC; HEIGHT: 0.45mm; MFG_NAME01: BOURNS; MFG_PN01: CR0402-JW-101GLF; ROHS: Yes; Tolerance: 5%
R89 = RES: RES MF ZERO OHM 1/10W -- 0603; AGILE_PN: 470-80866; ASSY_OPT: DNP; CAD_APPROVED: Yes; FPLIST: RC0603_OV,RC0603,R603-X2,0603_CC; HEIGHT: 0.6MM; MFG_NAME01: YAGEO AMERICA; MFG_PN01: RC0603FR-070RL; ROHS: Yes; Temp Range: –55 °C to +155 °C
R107 = RES: RES MF 10 OHM 1/16W 5% 0402; AGILE_PN: 470-75589; CAD_APPROVED: Yes; HEIGHT: 0.4MM; MFG_NAME01: BOURNS; MFG_PN01: CR0402-JW-100GLF; ROHS: Yes; Tolerance: 5%
R108 R109 = RES: RES MF 3.3 OHM 1/16W 5% 0402; AGILE_PN: 470-82606; CAD_APPROVED: Yes; HEIGHT: 0.4MM; MFG_NAME01: YAGEO AMERICA; MFG_PN01: RC0402JR-073R3L; Package Type: PCB Mount; ROHS: Yes; Temp Range: -55C to +155C; Tolerance: 5%
SH1-SH14 = RES_SHORT-2: ZERO OHM CUT TRACE 0402 PADS; NO PART TO ORDER; AGILE_PN: 470-76449; CAD_APPROVED: Yes; FPLIST: SH0402,SH0402_CC; HEIGHT: 0.1 MM; ROHS: Yes; SHORTED (DEFAULT): CLOSED
SH19 = RES_SHORT-2: ZERO OHM CUT TRACE 0603 PADS; NO PART TO ORDER; AGILE_PN: 470-80018; CAD_APPROVED: Yes; HEIGHT: 0.1MM; ROHS: Yes; SHORTED (DEFAULT): CLOSED
TP7 = TESTLOOP: TEST POINT PAD 40MIL DIA SMT, NO PART TO ORDER; AGILE_PN: 211-76643; CAD_APPROVED: Yes; HEIGHT: 0.1MM; MFG_NAME01: NOTACOMPONENT; MFG_PN01: NOTACOMPONENT; ROHS: Yes
U4 = LD1117AS18: IC VREG LDO 1A 3.3V SOT223; AGILE_PN: 312-80039; CAD_APPROVED: Yes; HEIGHT: 1.8MM; MFG_NAME01: ON SEMICONDUCTOR; ROHS: Yes; Temp Range: 0°C to +125°C; Temp_Range: 0°C to +125°C; VOLTAGE: 3.3V
C48 = CAP_NP: CAP CER 1000PF 50V 5% C0G 0402; AGILE_PN: 150-76334; ASSY_OPT: DNP; CAD_APPROVED: Yes; FPLIST: CC0402_25,CC0402_HD,0402_CC; HEIGHT: 0.55MM; MFG_NAME01: MURATA; MFG_PN01: GRM1555C1H102JA01D; Package Size: 0402; Package Type: 180mm Paper Tape; ROHS: Yes; Rated Voltage: 50V; Temp Range: -55C to +125C; Tolerance: 5%; VOLTAGE: 50V
C49 C50 = CAP_NP: CAP CER 12pF 50V 5% C0G AEC-Q200 0402; AGILE_PN: 150-80457; ASSY_OPT: DNP; CAD_APPROVED: Yes; FPLIST: CC0402_25,CC0402_HD,0402_CC,capc0402_l; HEIGHT: 0.55MM; MFG_NAME01: MURATA; MFG_PN01: GCM1555C1H120JA16D; Package Size: 0402; ROHS: Yes; Rated Voltage: 50V; Temp Range: -55C to +125C; Tolerance: 5%; VOLTAGE: 50V
D3 LED1 = LED: LED RED SGL 20mA 2V AEC-Q101 0603; AGILE_PN: 370-76847; CAD_APPROVED: Yes; HEIGHT: 0.55MM; MFG_NAME01: ROHM; Package Size: 0603 (1608 Metric); Rated Voltage: 2V; Temp Range: -40C to +100C; VOLTAGE: 2V
JP11 = CONN_HDR_2X1: HDR 1X2 TH 2MM SP 300H AU 102L; AGILE_PN: 210-80456; CAD_APPROVED: Yes; HEIGHT: 7.62MM; Jumper (Default): 1-2; MFG_NAME01: SAMTEC; ROHS: Yes; SILK: LED_RST; Temp_Range: -55°C to +105°C
JS1 = CONN_HDR_2X1: HDR 1X2 TH 2MM SP 217H AU 110L, NO PART TO ORDER; AGILE_PN: 210-80699; ASSY_OPT: DNP; CAD_APPROVED: Yes; FPLIST: sh_hdr102_2mm_bottom,sh_hdr102_2mm_bottom_a; HEIGHT: 5.2MM; MFG_PN01: NO_PART_TO_ORDER; ROHS: Yes; SHORTED (DEFAULT): CLOSED; SILK: VDD_MEM; Temp_Range: -55°C to +125°C
JS2 = CONN_HDR_2X1: HDR 1X2 TH 2MM SP 217H AU 110L, NO PART TO ORDER; AGILE_PN: 210-80699; ASSY_OPT: DNP; CAD_APPROVED: Yes; FPLIST: sh_hdr102_2mm_bottom,sh_hdr102_2mm_bottom_a; HEIGHT: 5.2MM; MFG_PN01: NO_PART_TO_ORDER; ROHS: Yes; SHORTED (DEFAULT): CLOSED; SILK: P_LED; Temp_Range: -55°C to +125°C
LED2 = LED: LED YELLOW CLEAR 20mA 2V 0603 SMT; AGILE_PN: 370-76774; CAD_APPROVED: Yes; HEIGHT: 0.8MM; MFG_NAME01: WURTH ELEKTRONIK EISOS GMBH & CO. KG (ELECTRONIC & ELECTROMEHANICAL COMP); MFG_PN01: 150060YS75000; Rated Voltage: 2V; Temp Range: -40C - 80C; VOLTAGE: 2V
LED3 = LED: LED ULTRA-BRIGHT GREEN SMT 0603; AGILE_PN: 370-75077; CAD_APPROVED: YES; HEIGHT: 0.8MM; MFG_NAME01: LITE ON; MFG_PN01: LTST-C190KGKT; ROHS: Yes; Rated Voltage: 2V; VOLTAGE: 2V
Q1 Q2 = NMOS_2N7002BKW_3P: TRAN NMOS SW FET 55V 210mA SOT23; AGILE_PN: 480-79704; CAD_APPROVED: Yes; HEIGHT: 1.1MM; MFG_NAME01: NEXPERIA; MFG_PN01: BSH111BKR; ROHS: Yes
R9 R11 R17 = RES: RES MF 10K 1/16W 1% 0402; AGILE_PN: 470-80452; ASSY_OPT: DNP; CAD_APPROVED: Yes; FPLIST: RC0402_25,RC0402_HD,0402_CC; HEIGHT: 0.40 MM; MFG_NAME01: NIC COMPONENTS CORP; MFG_PN01: NRCL04F1002TRF; PRIORITY_PN: 006-00552; ROHS: Yes; TOL: 1%; Tolerance: 1%
R10 = RES: RES MF 10K 1/16W 1% 0402; AGILE_PN: 470-80452; ASSY_OPT: DNP; CAD_APPROVED: Yes; FPLIST: RC0402_25,RC0402_HD,0402_CC; HEIGHT: 0.40 MM; MFG_NAME01: NIC COMPONENTS CORP; MFG_PN01: NRCL04F1002TRF; ROHS: Yes; Tolerance: 1%
R19 R20 R28 R29 = RES: RES MF 10K 1/16W 1% 0402; AGILE_PN: 470-80452; CAD_APPROVED: Yes; FPLIST: RC0402_25,RC0402_HD,0402_CC; HEIGHT: 0.40 MM; MFG_NAME01: NIC COMPONENTS CORP; MFG_PN01: NRCL04F1002TRF; ROHS: Yes; Tolerance: 1%
R25 = RES: RES 510 OHMS 1/16W 5% RC0402 ROHS; AGILE_PN: 470-76237; CAD_APPROVED: Yes; FPLIST: RC0402_25,RC0402_HD,0402_CC; HEIGHT: 0.4 MM; MFG_NAME01: YAGEO AMERICA; MFG_PN01: RC0402JR-07510RL; ROHS: Yes
SW1 = SW_SPNO_2P_GND6P: SW SPST PB 50MA 12V SMT; AGILE_PN: 510-77720; CAD_APPROVED: Yes; HEIGHT: 2.4MM; MFG_NAME01: E SWITCH; ROHS: Yes; SILK: RST_SW
SW2 = SW_SPNO_2P_GND6P: SW SPST PB 50MA 12V SMT; AGILE_PN: 510-77720; CAD_APPROVED: Yes; HEIGHT: 2.4MM; MFG_NAME01: E SWITCH; ROHS: Yes; SILK: PTC1 PB
SW3 = SW_SPNO_2P_GND6P: SW SPST PB 50MA 12V SMT; AGILE_PN: 510-77720; CAD_APPROVED: Yes; HEIGHT: 2.4MM; MFG_NAME01: E SWITCH; ROHS: Yes; SILK: PTC7_WUU0_P12 PB
TP8-TP13 = TESTLOOP: TEST POINT PAD 30MIL DIA SMT, NO PART TO ORDER; 3D_Mechanical_Footprint_File: http://fcl.am.freescale.net/ALLEGRO/step/tpad_030.STEP; AGILE_PN: 211-76642; CAD_APPROVED: Yes; HEIGHT: 0.1MM; MFG_NAME01: NOTACOMPONENT; MFG_PN01: NOTACOMPONENT; ROHS: Yes
TP15-TP18 = TEST_POINT: TEST POINT RECT 2P7X4P7 MM NO PART TO ORDER; AGILE_PN: 510-78183; CAD_APPROVED: Yes; HEIGHT: 0.127MM; MFG_NAME01: NA; MFG_PN01: NO PART TO ORDER1; ROHS: Yes; SILK: GND
U5 = AT25XE161D_8P_EP: IC MEM SPI SERIAL FLASH 16MBIT 133MHZ 1.65-3.6V UDFN8; 3D_Mechanical_Footprint_File: http://fcl.am.freescale.net/ALLEGRO/step/udfn8_0p5_3x2mm.STEP; AGILE_PN: 334-77908; CAD_APPROVED: Yes; HEIGHT: 0.6 MM; MFG_NAME01: Adesto Technologies Corporation, Inc; Package Size: 8-UFDFN Exposed Pad; ROHS: Yes; Supply Voltage: 1.65V ~ 3.6V; Temp Range: -40  °C to +85 °C
Y1 = XTAL_13: XTAL 32MHz 8pF AEC-Q200 SMT; AGILE_PN: 230-78528; CAD_APPROVED: Yes; HEIGHT: 0.35MM; MFG_NAME01: NDK; MFG_PN01: NX1612SA 32MHZ EXS00A CS14160; Package Size: 1.6 x 1.2 x 0.3 mm; ROHS: Yes; SILK: 32M; Temp Range: -40°C to +125°C
Y2 = XTAL: XTAL 32.768KHz FIXED 12.5pF -- AEC-Q200 SMT; 3D_Mechanical_Footprint_File: http://fcl.am.freescale.net/ALLEGRO/xtal2_2x1p2_sm.STEP; AGILE_PN: 230-78455; CAD_APPROVED: YES; Frequency Tolerance: +/- 20 PPM; HEIGHT: 0.6MM; MFG_NAME01: NDK; MFG_PN01: NX2012SE 32.768kHz EXS00A-MU01517; ROHS: YES; SILK: 32K; Temp Range: -40 C TO -125 C
Y3 = O4-0: OSC TCXO 32MHz 1.8V AEC-Q100/200 SMD; AGILE_PN: 230-78487; ASSY_OPT: DNP; CAD_APPROVED: YES; HEIGHT: 0.8MM; MFG_NAME01: NDK; MFG_PN01: NT2016SB-32MHZ-NSA3561B; ROHS: YES; Temp Range: -30 C to +85 C; VOLTAGE: 1.8V

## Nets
1V8_DCDC: C5.1 C6.1 JP10.1 L1.2 R89.2
3V3_MIKROE: J1.7 SH12.1
5V_MIKROE: J2.7 SH14.2
GND: BT1.2(-) BT2.2(-) C1.2 C2.2 C5.2 C6.2 C7.2 C8.2 C9.2 C10.2 C11.2 C12.2 C13.2 C14.2 C15.2 C16.2 C17.2 C18.2 C19.2 C20.2 C21.2 C22.2 C23.2 C24.2 C25.2 C26.2 C27.2 C28.2 C29.2 C30.2 C31.2 C32.2 C33.2 C34.2 C35.2 C36.2 C37.2 C38.2 C39.2 C40.2 C41.2 C42.2 C43.2 C44.2 C45.2 C46.2 C47.2 C49.2 C50.2 C97.2 C98.2 C99.2 C100.2 C101.2 C102.2 J1.8 J2.8 J7.2(GND1) J7.3(GND2) J8.2(GND1) J8.3(GND2) LED3.C(CATHODE) Q1.2(SOURCE) Q2.2(SOURCE) R28.1 R29.1 R94.2 R95.2 R110.2 SW1.1(S1) SW1.G1(GND1) SW1.G2(GND2) SW1.G3(GND3) SW1.G4(GND4) SW2.1(S1) SW2.G1(GND1) SW2.G2(GND2) SW2.G3(GND3) SW2.G4(GND4) SW3.1(S1) SW3.G1(GND1) SW3.G2(GND2) SW3.G3(GND3) SW3.G4(GND4) TP15.1 TP16.1 TP17.1 TP18.1 U1.19(VSS_DCDC) U1.49(VSS/VREFL) U2.1(GND) U2.2(GND) U2.3(GND) U2.4(GND) U2.6(GND_5) U2.7(GND_6) U2.9(GND_7) U2.10(GND_8) U2.12(GND_9) U2.13(GND_10) U2.15(GND_11) U2.20(GND_12) U2.21(GND_13) U2.23(GND_14) U2.24(GND_15) U2.25(EP) U4.1(GND) U5.4(GND) U5.9(EP) U21.2(GND1) U21.4(GND2) Y1.2 Y1.4 Y3.1(EN/~{DIS}) Y3.2(DGND) ; also on sheet 6 7 8
P3V3: JP19.3
P3V3_BATT: BT1.1(+) BT2.1(+) D2.A
P3V3_LDO: D1.C JP19.1 SH19.2
P5V: C23.1 D16.C SH14.1 TP7.1(Pin1) U4.3(VIN) ; also on sheet 6 8
P5V_CAN: D16.A ; also on sheet 8
VBAT: C25.1 D2.C JP2.1(A1)
VDD_ANA: C34.1 JP9.2 U1.29(VDD_ANA)
VDD_CORE: C13.1 C14.1 C16.1 C17.1 TP1.1(Pin1) U1.16(VDD_CORE_1) U1.41(VDD_CORE_2)
VDD_DCDC: C30.1 C31.1 C47.1 R9.1 R24.1 R108.2 U1.21(VDD_DCDC) Y3.4(VCC)
VDD_IC: JP2.2(B1) JP2.3(A2) R107.1
VDD_IO_ABC: C32.1 C33.1 JP8.2 U1.4(VDD_IO_ABC)
VDD_LDO_CORE: C35.1 C36.1 C37.1 JP4.1 U1.15(VDD_LDO_CORE)
VDD_MEM: C44.1 JS1.1 R10.1 R11.1 R19.1 R20.1 U5.8(VCC)
VDD_PA_2G4: C7.1 C18.1 L2.1 R89.1 TP3.1(Pin1) U1.36(VPA_2P4GHZ)
VDD_REG: JP3.2 JP7.1 JP8.1 JP9.1 JP10.3
VDD_RF: C40.1 C41.1 R109.2 U1.34(VDD_RF)
VDD_SWITCH: C26.1 C27.1 JP1.1 U1.6(VDD_SWITCH)
VOUT_SYS/VDD_SYS: C38.1 C39.1 U1.22(VDD_SYS)
ADC0_A13: R8.2 SH2.2
ADC_IN: J1.1 SH2.1
ANT: L2.2 L3.1 U1.35(ANT_2P4GHZ)
ANT_A: E1.2
ANT_B: E2.2
ANT_RF: C1.1 L3.2 L10.1
CS: R11.2 R16.2 R21.2 TP11.1(Pin1) U5.1(~{CS})
DCDC_LX: L1.1 R1.1 U1.20(DCDC_LX)
EXTAL32K: C50.1 R31.2 Y2.2
EXTAL_32M: R32.2 Y1.3
EXTAL_RF: C48.1 R32.1 U1.33(EXTAL)
H/RST: R18.2 R20.2 U5.7(~{HOLD}/~{RESET}/IO3)
L_R1: LED1.A(ANODE) R22.2
L_Y2: LED2.A(ANODE) R23.2
LED1_R: LED1.C(CATHODE) Q1.3(DRAIN)
LED1_R1: Q1.1(GATE) R26.2 R28.2
LED2_Y: LED2.C(CATHODE) Q2.3(DRAIN)
LED2_Y2: Q2.1(GATE) R27.1 R29.2
LED_RST: D3.A(ANODE) R24.2
LLWU/NMI_b: J2.2 SH5.2
LPI2C1_SCL: J2.5 SH11.2
LPI2C1_SDA: J2.6 SH13.2
LPSPI1_PSC0: J1.3 SH4.1
LPSPI1_SCK: J1.4 SH6.1
LPSPI1_SIN: J1.5 SH8.1
LPSPI1_SOUT: J1.6 SH10.1
LPUART0_RX: J2.3 SH7.2
LPUART0_TX: J2.4 SH9.2
P_LED: JS2.1 R22.1 R23.1 R25.1
P_VDD_SWITCH: JP1.2 JP3.1 L13.2
PO_LED: LED3.A(ANODE) R25.2
PTA0/SWD_DIO: U1.8(PTA0/CMP0_OUT/~{LPUART0_CTS}/RF_GPO_11/TPM0_CH4/FLEXIO0_D0/SWD_DIO/WUU0_P0) ; also on sheet 7
PTA1/SWD_CLK: U1.9(PTA1/CMP1_OUT/~{LPUART0_RTS}/RF_GPO_10/TPM0_CH5/FLEXIO0_D1/SWD_CLK) ; also on sheet 7
PTA4/SWO/BOOT_CFG: U1.10(PTA4/ADC0_A10/CMP0_IN0/ATX0/RF_GPO_9/TPM0_CLKIN/TRACE_SWO/FLEXIO0_D4/BOOT_CONFIG/WUU0_P2/RF_XTAL_OUT_ENABLE) ; also on sheet 7
PTA16: SH7.1 U1.11(PTA16/ADC0_A12/NVM_TM2/LPSPI0_PCS0/~{EWM0_OUT}/LPI2C0_SCLS/TPM0_CH4/LPUART0_RX/RF_GPO_8/FLEXIO0_D5/RF_NOT_ALLOWED) ; also on sheet 8
PTA17: SH9.1 U1.12(PTA17/ADC0_A13/NVM_TM3/LPSPI0_SIN/EWM0_IN/LPI2C0_SDAS/TPM0_CH5/LPUART0_TX/RF_GPO_7/RF_GPO_8/FLEXIO0_D6/RF_EXT_XTAL_REQUEST/RF_GPO_7/WUU0_P3/RF_NOT_ALLOWED) ; also on sheet 8
PTA18: C100.1 R94.1 U1.13(PTA18/CMP1_IN1/LPSPI0_SOUT/~{LPUART0_CTS}/LPI2C0_SDA/TPM0_CH3/RF_GPO_0/LPUART0_RX/SPC0_LPREQ) U2.17(CONTROL_1)
PTA19: C101.1 R91.2 U1.14(PTA19/CMP1_IN0/ATX1/LPSPI0_SCK/~{LPUART0_RTS}/LPI2C0_SCL/TPM0_CH2/RF_GPO_1/NVM_SDO/WUU0_P4) U2.18(CONTROL_2)
PTA20: C102.1 R95.1 U1.17(PTA20/ADC0_A14/CMP0_IN3/LPSPI0_PCS2/LPUART0_TX/EWM0_IN/TPM0_CH1/RF_GPO_2//FLEXIO0_D7) U2.19(CONTROL_3)
PTA21: C43.1 R8.1 U1.18(PTA21/ADC0_A15/CMP0_IN2/LPSPI0_PCS3/LPUART0_RX/~{EWM0_OUT}/TPM0_CH0/RF_GPO_3/RF_GPO_7/FLEXIO0_D8/RF_GPO_10/WUU0_P5)
PTB0: R16.1 SH4.2 U1.46(PTB0/ADC0_B10/LPSPI1_PCS0/TPM1_CH0/FLEXIO0_D26/WUU0_P13)
PTB1: R13.1 SH8.2 U1.47(PTB1/ADC0_B11/LPSPI1_SIN/TPM1_CH1/FLEXIO0_D27)
PTB2: R12.1 SH6.2 U1.48(PTB2/ADC0_B12/LPSPI1_SCK/LPUART1_TX/TPM1_CH2/FLEXIO0_D28)
PTB3: R14.1 SH10.2 U1.1(PTB3/ADC0_B13/LPSPI1_SOUT/LPUART1_RX/TPM1_CH3/FLEXIO0_D29/WUU0_P14)
PTB4: JP24.3 R18.1 R21.1 U1.2(PTB4/NVM_TM0/LPSPI1_PCS3/~{LPUART1_CTS}/LPI2C1_SDA/I3C0_SDA/TRGMUX0_IN0/FLEXIO0_D30/WUU0_P15)
PTB5: R15.1 SH11.1 U1.3(PTB5/NVM_TM1/LPSPI1_PCS2/~{LPUART1_RTS}/LPI2C1_SCL/I3C0_SCL/TRGMUX0_OUT0/FLEXIO0_D31)
PTC0: JP23.3 R26.1 U1.37(PTC0/LPSPI1_PCS2/CAN0_TX/I3C0_SDA/TPM1_CH0/LPI2C1_SCL/FLEXIO0_D16/WUU0_P7)
PTC1: C45.1 R9.2 SW2.2(S2) TP9.1(Pin1) U1.38(PTC1/LPSPI1_PCS3/CAN0_RX/I3C0_SCL/TPM1_CH1/LPI2C1_SDA/FLEXIO0_D17/WUU0_P8)
PTC2: C21.1 U1.39(PTC2/LPSPI1_SOUT/LPUART1_RX/LPI2C1_SCLS/TPM1_CH2/I3C0_PUR/FLEXIO0_D18/WUU0_P9) ; also on sheet 8
PTC3: C22.1 U1.40(PTC3/LPSPI1_SCK/LPUART1_TX/LPI2C1_SDAS/TPM1_CH3/FLEXIO0_D19) ; also on sheet 8
PTC4: U1.42(PTC4/LPSPI1_SIN/CAN0_TX/LPI2C1_SCL/TPM2_CH0/FLEXIO0_D20/WUU0_P10) ; also on sheet 8
PTC5: U1.43(PTC5/LPSPI1_PCS0/CAN0_RX/LPI2C1_SDA/TPM1_CH4/TPM2_CH1/FLEXIO0_D21) ; also on sheet 8
PTC6: R27.2 U1.44(PTC6/ADC0_A8/LPSPI1_PCS1/TPM1_CH5/FLEXIO0_D22/WUU0_P11)
PTC7: C46.1 R17.2 SH5.1 SW3.2(S2) TP12.1(Pin1) U1.45(PTC7/DISABLED/TRGMUX0_IN3/TRGMUX0_OUT3/SFA0_CLK/TPM1_CLKIN/TPM2_CLKIN/FLEXIO0_D23/WUU0_P12/~{NMI}/RF_NOT_ALLOWED)
PTD2: JP23.1 U1.25(PTD2/ADC0_A6/LPTMR0_ALT3/TAMPER0/RF_GPO_5)
PTD2/TMP1_CH0: JP23.2 SH3.1
PTD3: JP24.1 U1.26(PTD3/ADC0_B6/LPTMR1_ALT3/TAMPER1/RF_GPO_6/TRGMUX0_IN2)
PTD3/I2C1_SDA: JP24.2 SH13.1
PTD4_XTAL32K: R30.1 U1.27(PTD4/XTAL32K/LPTMR0_ALT2/TAMPER2)
PTD5_EXTAL32K: R31.1 U1.28(PTD5/EXTAL32K/LPTMR1_ALT2)
PWM/TMP1_CH0: J2.1 SH3.2
RESET: J1.2 SH1.1
RF1: R92.1 R110.1 U2.14(RF1)
RF4: C98.1 R93.1 U2.5(RF4)
RF_50: C2.1 C3.1 L10.2 U21.1(IN)
RF_A: C9.1 L11.1 U2.11(RF2)
RF_ANT_1: C10.1 E1.1 L11.2
RF_ANT_2: C12.1 E2.1 L12.2
RF_B: C11.1 L12.1 U2.8(RF3)
RF_SMA_1: C97.1 J7.1(CTR) R92.2
RF_SMA_2: C99.1 J8.1(CTR) R93.2
RST_TGTMCU_b: JP11.2 SH1.2 SW1.2(S2) U1.23(PTD0/ADC0_A5/~{RESET}) ; also on sheet 7
SCK: R10.2 R12.2 TP8.1(Pin1) U5.6(SCK)
SI: R14.2 TP10.1(Pin1) U5.5(SI/IO0)
SO: R13.2 TP13.1(Pin1) U5.2(SO/IO1)
SW_50: C3.2 U2.22(RF_COM) U21.3(OUT)
SWITCH_WAKEUP_B: TP4.1(Pin1) U1.5(~{SWITCH_WAKEUP})
V_BRD: C19.1 C20.1 C42.1 JP2.4(B2) JP19.2 JS1.2 JS2.2 R17.1 R91.1 SH12.2 SH19.1 U2.16(VDD) ; also on sheet 7 8
V_LDO_OUT: C24.1 D1.A U4.2(VOUT) U4.4(TAB)
V_SEC: JP4.2 JP6.1 JP10.2
VOUT_SWITCH: C28.1 C29.1 JP3.3 U1.7(VOUT_SWITCH)
VREF_OUT: C15.1 TP2.1(Pin1) U1.30(VREF_OUT)
WP: R15.2 R19.2 U5.3(~{WP}/IO2)
XTAL32K: C49.1 R30.2 Y2.1
XTAL_RF: U1.32(XTAL) Y1.1
N23403057: JP7.2 R108.1
N23403396: JP6.2 R109.1
N23407124: D3.C(CATHODE) JP11.1
N23407644: C48.2 Y3.3(OUT)
N23411769: C8.1 R1.2
N23959568: L13.1 R107.2

Not connected (* = marked no-connect by the designer): BMP1 1(NC)*; BMP2 1(NC)*; BMP3 1(NC)*; BMP4 1(NC)*; U1 24(PTD1/ADC0_B5/SPC0_LPREQ/~{NMI}/RF_GPO_4)* 31(XTAL_OUT)*

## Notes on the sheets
sheet 1
- Table of Contents
- Revisions & Change Log
- 1
- Title
- Rev
- Description
- Date
- Approved
- 2
- Block Diagram
- X1
- First Release
- 05/13/21
- 3
- KW45B41Z MCU
- X2
- J7 replaced for U.FL connetor
- 05/28/21
- 22pF ser caps added to RF ports
- 4
- Power Management
- 1x2,1x3 headers replaced for 2MM
- 5
- LED, Memory, Misc
- X3
- U6 changed for 100pin version
- 06/02/21
- 6
- MCU-Link
- Matching network optimized
- 7
- MCU-Link SWD
- X4
- RF switch updates
- 07/13/21
- 8
- MCU-Link IO
- A
- Released files
- 08/04/21
- A1
- Antenna Control Table updated
- 10/25/21
- Matching network updated
- A2
- L2 updated to 15nH
- 12/02/21
- PWR jumpers updated
- Pulldown for MCULink HW VER
- 12/20/21
- CAN support
- U1 changed for 48-pin version
- C30 changed for 10uF
- 100k pul-up TGTMXCU_TX line
- MCULink HW VER config updated
- 01/14/22
- Block diagram updated
- SH19 added
- 01/25/22
- B
- Matching values updated
- 03/30/22
- M.R.
- (C10, C12, R2, R3)
- Net HW_VER renamed to HW_VER_8
- Added JP13 & JP14
- PTA16 & PTA17 for LPUART0
- C1 & L10 updated. R5 Removed
- C100-C102 changed to 100pF
- PTD2 & PTD3 to J2 connector
- 04/08/22
- LED2 drive through PTC6
- JP22 & JP23 added
- 04/21/22
- R107, R108 & L13 added
- R109 added
- 04/25/22
- C38,C32,C34 values updated
- 04/29/22
- BOOT CONFIG section updated
- 05/25/22
- C
- R92 to DNP
- 12/20/22
- E.L.
- Replace C96 and populate R110
- P5V_CAN tied to P5V
- KW45B41Z-LOC
  Bluetooth Smart/Generic FSK
- JP25 added for RST disable @U11
- JP2 replaced for a 2x2 header
- Swap CAN from PTC0/1 to PTC4/5
- U1 update MPN according DS
- 01/20/23
- U21 added to RF path - DNP
- C1
- RF matching updated
- C1,C2,L10
- 02/24/22
- M.R.
- C2
- RF matching updated
- C1,C2,L10
- 08/01/23
- M.R.
- (KW45 Localization Kit)
- BL Edge Processing
sheet 2
- NOTES
- 1. Unless Otherwise Specified:
- All resistors are in ohms, 5%, 1/8 Watt
- All capacitors are in uF, 20%, 50V
- Page[4]
- All voltages are DC
- All polarized capacitors are aluminum electrolytic
- Page[4]
- 2. Interrupted lines coded with the same letter or letter
      combinations are electrically connected.
- Page[5]
- 3. Device type number is for reference only. The number
      varies with the manufacturer.
- Page[4]
- Page[3]
- 4. Special signal usage:
- Page[5]
- Page[4]
- _B Denotes - Active-Low Signal
- Page[4]
- <> or [] Denotes - Vectored Signals
- Page[6-8]
- 5. Interpret diagram in accordance with American
  National Standards Institute specifications, current
  revision, with the exception of logic block symbology.
- Page[5]
- Page[6]
- Page[4]
- Page[6]
- Page[5]
- NOTES
- This Color is for User Notes
- Page[5]
- Page[5]
- Page[7]
- Page[5]
- This Color is for CAD/LAY Notes
- This Color is custom Shield Notes
- This Color is for Silk
- Page[5]
- This Color is for DNP components
- Page[8]
- Page[5]
- Target MCU: KW45B41Z p[3]
  Debug MCULink: LPC55S69  p[6]
- Page[4]
- REF DES
- SHORTED(DEFAULT)
- PAGE NAME
- SH1,SH2,SH3,SH4,SH5,SH6,SH7,
  SH8,SH9,SH10,SH11,SH12,SH13,
  SH14,SH19
- CLOSED
- 04. PWR MANAGEMENT
- JS1,JS2
- CLOSED
- 05. LED, MEMORY, MISC
- SH15
- CLOSED
- 07. MCU Link SWD
- BUMPON added to each bottom side corner
- Jumper Table
- DNP Table
- REF DES
- ASSY_OPT
- PAGE NAME
- REF DES
- JUMPER(DEFAULT)
- PAGE NAME
- C1,C4,C10,C12,C16,C21,C22
- DNP
- 03 - MKW45B41Z MCU
- JP1,JP3,JP4,JP6,JP7,JP8,JP9,JP10
- 1-2
- 04 - PWR MANAGEMENT
- R89,C27,C29,C37,C38,BT1
- DNP
- 04 - PWR MANAGEMENT
- JP23,JP24
- 1-2
- 04 - PWR MANAGEMENT
- JP2
- 2-4
- 04 - PWR MANAGEMENT
- R9,R10,R11,R15,R17,R18,
  R21,C48,C49,C50,Y3,JS1,JS2
- DNP
- 05 - LED, MEM & MISC
- JP11
- 1-2
- 05 - LED, MEM & MISC
- JP12,JP21,JP22
- OPEN
- 06 - MCU LINK
- R41,R42,R55,R56,R87,R88,
  C77,C78,J4
- DNP
- 06 - MCU LINK
- JP16
- 1-OPEN
- 07 - MCU LINK SWD
- JP17
- OPEN
- 07 - MCU LINK SWD
- R65,R66,C113
- DNP
- 07 - MCU LINK SWD
- JP18,JP25
- 1-2
- 07 - MCU LINK SWD
- JP13, JP14
- 1-2
- 08 - MCU LINK IO
sheet 3
- Custom shield.
- Custom shield.
- DCDC Inductor
- CAD note: Place C13 & C14 caps close to pin14
- (to DCDC_LX inductor)
- MLZ2012A1R0WTD25
  L1 AUTO PART
- CAD note: Place C16 & C17 caps close to pin33
- CAD note: Place ALL caps close to MCU
- SWD_DIO
- SWD_CLK
- SWD
- SWO/BOOT_CONF
- LPUART0_RX
- LPUART0
- LPUART0_TX
- VDD_SYS = 1.71V -2.75V
- RF_GPO0
- RF_GPO1/TMP0_CH2
- RF_GPO2
- LPSPI1_PCS0
- LPSPI1_SIN
- LPSPI1_SK
- LPSPI1_SOUT
- LPSPI1
- LPSPI1_PCS3/I2C1_SDA
- LPSPI1_PCS2/I2C1_SCL
- I2C1
- TMP1_CH0
- UART1_RX
- WUU0_P8
- UART1_TX
- LPUART1
- CAN0_TX
- CAN0_RX
- TMP1_CH5
- WUU0_P12
- Custom shield.
- RST
- RST
- XTAL32K
- EXTAL32K
- Custom shield.
- i
- CAD Note:
- VDD_PA_2G4 enable +10dBm RF output
- Keep the same length of the RF signals
  RF1 and RF4 in the layout
- LQG15HZ15NJ02D
  L2 AUTO PART
- VCO leakage decoupling capacitors.
- RF SWITCH
- MLG1005S1N0CT000
  L10 AUTO PART
- GCM1555C1H150GA16D
  C3 AUTO PART
- CAD Note: Keep ANT
  trace short  as
  possible
- ANTENNA A
- RC0402JR-070RL
  L3  (Resistor)
- LQW15AN2N2C10
  L11,L12
  (Inductors)
- GCM1555C1H1R0BA16
  C10,C12
- ANTENNA B
- CAD Note:
- Keep the same length of the RF signals
  RF_A and RF_B in the layout
- QSCF201Q4R3A1GV001T
  C1 AUTO PART
- QSCF251Q2R7A1GV001T
  C2 AUTO PART
- Custom shield.
- ANTENNA CONTROL
- Antenna Matching Alt Parts
- MODE
- CTL3
- CTL2
- CTL1
- L11 & L12 MPN:L-07C2N2SV6T
- SMA1
- RF1
- L
- L
- H
- C10 & C12 MPN:L-500R07S1R0BV4T
- ANT_A
- RF2
- L
- H
- L
- ANT_B
- RF3
- L
- H
- H
- H
- L
- L
- RF_GPO0
- SMA2
- RF4
- L
- L
- L
- RF_GPO1/TMP0_CH2
- RF_GPO2
- CAD Note:
- ALL OFF
- H
- H
- H
- L
- H
- L
- 50 ohm controlled
  impedence line
- Keep the same length of
  the RF signals
  RF1 and RF4 in the layout
sheet 4
- POWER MANAGEMENT
- SECONDARY
  OPTION
- COIN CELL
  HOLDER
- CAD note: BT2 should be should be overlapped w/BT1
           Use secondary (bottom) side for placement
- POWER CONFIGURATION
- VDD_BRD
    JP10
- DEFAULT CONFIG :
- DCDC Mode
- DCDC Mode
- 1-2
- P3V3 (JP2) : 1-2
- VDD_SWITCH (JP1) : 1-2
- VDD_REG (JP3) : 1-2
- VDD_LDO_CORE (JP4): 1-2
- VDD_RF (JP6) : 1-2
- Bypass Mode
- 2-3
- VDD_DCDC (JP7) : 1-2
- VDD_ANA (JP9) : 1-2
- VDD_IO_ABC (JP8) : 1-2
- i
- TP3 enables VDD_PA_2G4 for +10dBm RF output
- VDD_SWITCH
- VOUT_SWITCH
- MCU_VDDs
- CAD note: Place ALL caps close to MCU
- Dec Caps inside the custom shield.
- (to DCDC_LX inductor)
- (VDD_IO_D)
- CAD note: Place ALL caps close to MCU
- Dec Caps inside the custom shield.
- 6.3V
- JP4, JP6, JP7 & JP8 used for current measurements
- CAD note: Place ALL caps close to MCU
- Dec Caps inside the custom shield.
- TMP1_CH0
- Mikroe Connector
- I2C1_SDA
- AN
- PWM
- RST
- MCU RST
- WUU0_P12
- INT
- CS
- SCK
- LPSPI1_PCS0
- LPSPI1_SK
- UART0_RX
- UART0_TX
- RX
- TX
- MISO
- LPSPI1_SIN
- I2C1_SCL
- SCL
- MOSI
- LPSPI1_SOUT
- SDA
- VDD_TARGET
- +5V
- GND
- GND
sheet 5
- 16Mbit (2MB) FLASH
- INTERRUPT PUSH BUTTONS
- TMP2_CH1
- LPSPI1_SK
- LPSPI1_SIN
- LPSPI1_SOUT
- LPSPI1_PCS2/I2C1_SCL
- LPSPI1_PCS3/I2C1_SDA
- LPSPI1_PCS0/TPM1_CH0
- WUU0_P12
- LPSPI1_PCS3
- LEDS
- RESET
- POWER ON
  INDICATOR
- USER LEDs
- TMP1_CH0
- TMP1_CH5
- MCU RST
- Custom shield.
- IN CIRCUIT TEST
  GND PROBING
- CLOCK SECTION
- TCXO
- 32KHz CLOCK CIRCUIT
- 32MHz CLOCK CIRCUIT
